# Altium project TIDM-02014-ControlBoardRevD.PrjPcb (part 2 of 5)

## Sheet power_ls.SchDoc: Low-Side Power Rail
size 431 x 279 mm; Date: Not shown in title block; ApprovedBy: Not shown in title block; CheckedBy: Not shown in title block; Author: Not shown in title block; CompanyName: Not shown in title block; DrawnBy: Panacek; Organization: Not shown in title block; Address1: Not shown in title block; Address2: Not shown in title block; Address3: Not shown in title block; Address4: Not shown in title block; DocumentNumber: 3; Revision: Use project parameter SCH_Rev; SheetNumber: 3; SheetTotal: 19; PageSetup: Record=PageOptions¦CenterHorizontal=True¦CenterVertical=True¦PrintScale=1.00¦XCorrection=1.00¦YCorrection=1.00¦PrintKind=0¦BorderSize=5000000¦LeftOffset=0¦BottomOffset=0¦Orientation=2¦PaperLength=1000¦PaperWidth=1000¦Scale=100¦PaperSource=15¦PrintQuality=600¦MediaType=1¦DitherType=10¦PaperKind=Letter¦PrintScaleMode=1
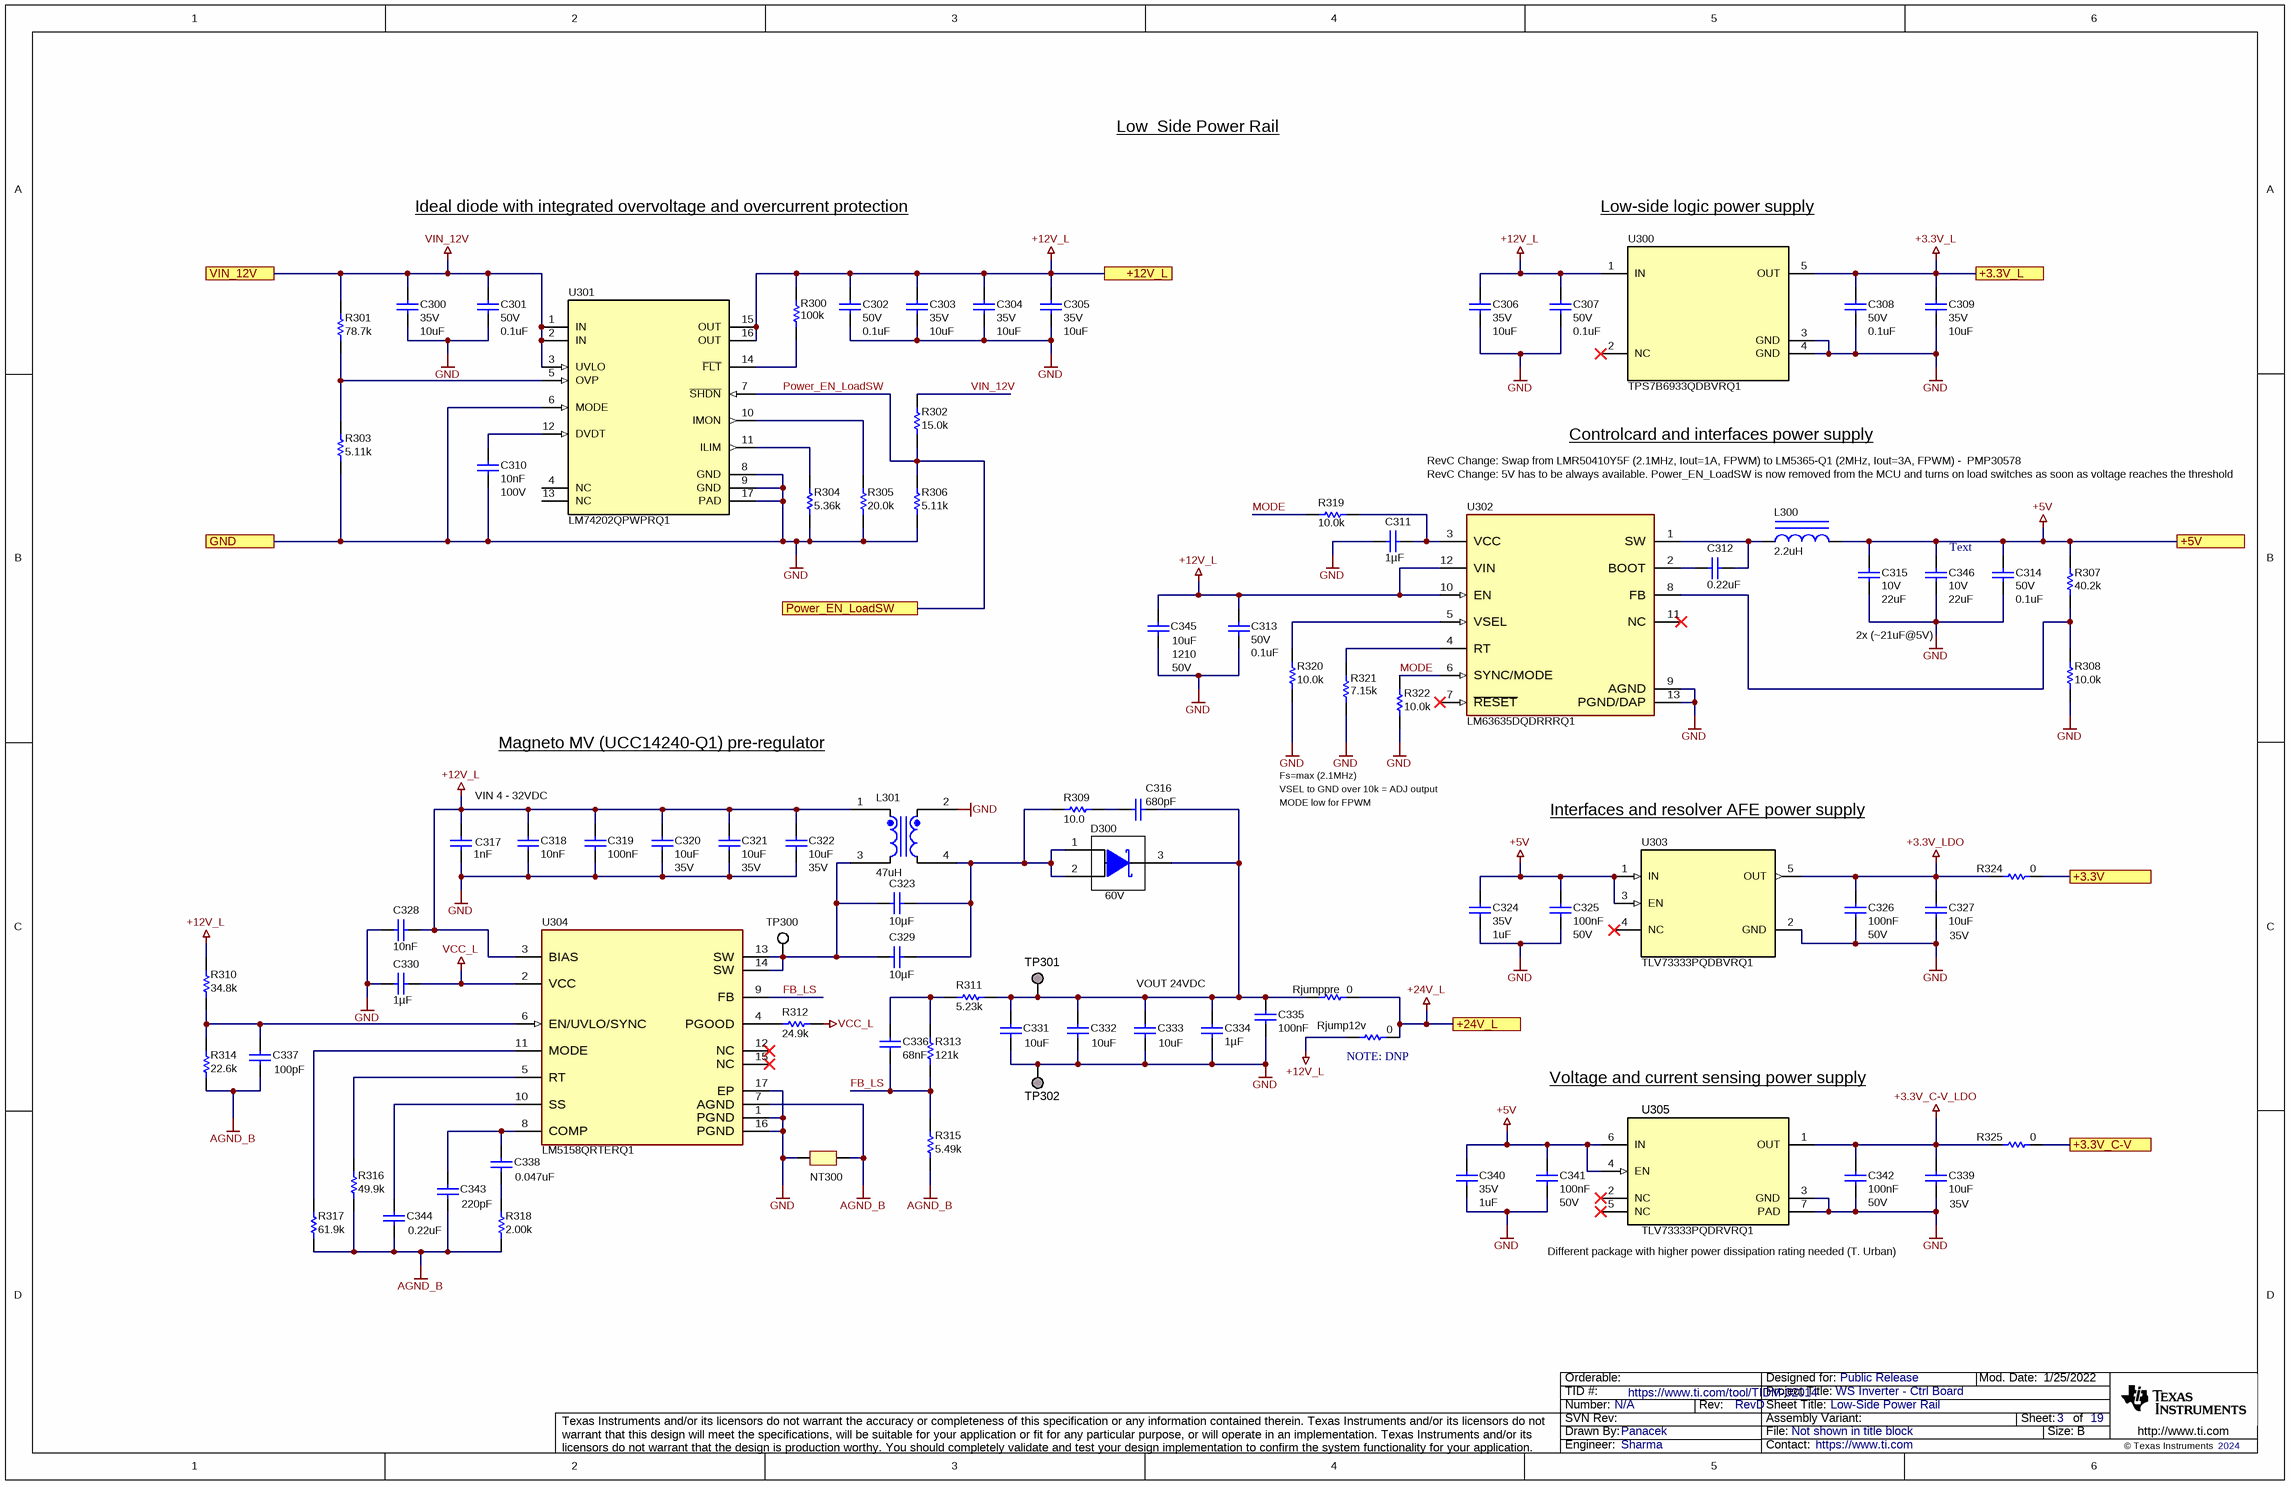
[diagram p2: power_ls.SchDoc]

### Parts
C300  VDC_V: 35V  ValueDisplayed: 10uF  [0603]  (hidden comment: GRM188R6YA106MA73D)
C301  VDC_V: 50V  ValueDisplayed: 0.1uF  [0603]  (hidden comment: CGA3E2X7R1H104K080AA)
C302  VDC_V: 50V  ValueDisplayed: 0.1uF  [0603]  (hidden comment: CGA3E2X7R1H104K080AA)
C303  VDC_V: 35V  ValueDisplayed: 10uF  [0603]  (hidden comment: GRM188R6YA106MA73D)
C304  VDC_V: 35V  ValueDisplayed: 10uF  [0603]  (hidden comment: GRM188R6YA106MA73D)
C305  VDC_V: 35V  ValueDisplayed: 10uF  [0603]  (hidden comment: GRM188R6YA106MA73D)
C306  VDC_V: 35V  ValueDisplayed: 10uF  [0603]  (hidden comment: GRM188R6YA106MA73D)
C307  VDC_V: 50V  ValueDisplayed: 0.1uF  [0603]  (hidden comment: CGA3E2X7R1H104K080AA)
C308  VDC_V: 50V  ValueDisplayed: 0.1uF  [0603]  (hidden comment: CGA3E2X7R1H104K080AA)
C309  VDC_V: 35V  ValueDisplayed: 10uF  [0603]  (hidden comment: GRM188R6YA106MA73D)
C310  Cap_F: 10nF  VDC_V: 100V  [0603]  (hidden comment: CGA3E2X7R2A103K080AA)
C311  Cap_F: 1µF  [0603]  (hidden comment: CGA3E1X7R1V105K080AC)
C312  ValueDisplayed: 0.22uF  [0603]  (hidden comment: GCM188R71E224KA55D)
C313  VDC_V: 50V  ValueDisplayed: 0.1uF  [0603]  (hidden comment: CGA3E2X7R1H104K080AA)
C314  VDC_V: 50V  ValueDisplayed: 0.1uF  [0603]  (hidden comment: CGA3E2X7R1H104K080AA)
C315  VDC_V: 10V  ValueDisplayed: 22uF  [1210_270]  (hidden comment: GRM32ER71A226ME20L)
C316  ValueDisplayed: 680pF  [0603]  (hidden comment: C0603C681J5GACTU)
C317  Cap_F: 1nF  [0603]  (hidden comment: GRM1885C1H102JA01D)
C318  Cap_F: 10nF  [0603]  (hidden comment: CGA3E2X7R2A103K080AA)
C319  Cap_F: 100nF  [0603]  (hidden comment: CGA3E2X7R1H104K080AA)
C320  ValueDisplayed: 10uF  VDC_V: 35V  [0603]  (hidden comment: GRM188R6YA106MA73D)
C321  ValueDisplayed: 10uF  VDC_V: 35V  [0603]  (hidden comment: GRM188R6YA106MA73D)
C322  ValueDisplayed: 10uF  VDC_V: 35V  [0603]  (hidden comment: GRM188R6YA106MA73D)
C323  ValueDisplayed: 10µF  [1206_190]  (hidden comment: CGA5L1X7R1H106K160AC)
C324  VDC_V: 35V  ValueDisplayed: 1uF  [0603]  (hidden comment: CGA3E1X7R1V105K080AC)
C325  Cap_F: 100nF  VDC_V: 50V  [0603]  (hidden comment: CGA3E2X7R1H104K080AA)
C326  Cap_F: 100nF  VDC_V: 50V  [0603]  (hidden comment: CGA3E2X7R1H104K080AA)
C327  ValueDisplayed: 10uF  Value2: 35V  [0603]  (hidden comment: GRM188R6YA106MA73D)
C328  Cap_F: 10nF  [0603]  (hidden comment: CGA3E2X7R2A103K080AA)
C329  ValueDisplayed: 10µF  [1206_190]  (hidden comment: CGA5L1X7R1H106K160AC)
C330  Cap_F: 1µF  [0603]  (hidden comment: CGA3E1X7R1V105K080AC)
C331  ValueDisplayed: 10uF  [1210_270]  (hidden comment: GRM32ER71H106KA12L)
C332  ValueDisplayed: 10uF  [1210_270]  (hidden comment: GRM32ER71H106KA12L)
C333  ValueDisplayed: 10uF  [1210_270]  (hidden comment: GRM32ER71H106KA12L)
C334  Cap_F: 1µF  [0805_HV]  (hidden comment: CGA4J3X7R1H105K125AB)
C335  Cap_F: 100nF  [0603]  (hidden comment: CGA3E2X7R1H104K080AA)
C336  Cap_F: 68nF  [0603]  (hidden comment: CGA3E2X7R1H683K080AA)
C337  ValueDisplayed: 100pF  [0603]  (hidden comment: CGA3E2NP01H101J080AA)
C338  ValueDisplayed: 0.047uF  [0603]  (hidden comment: CGA3E2X7R1H473K080AA)
C339  ValueDisplayed: 10uF  Value2: 35V  [0603]  (hidden comment: GRM188R6YA106MA73D)
C340  VDC_V: 35V  ValueDisplayed: 1uF  [0603]  (hidden comment: CGA3E1X7R1V105K080AC)
C341  Cap_F: 100nF  VDC_V: 50V  [0603]  (hidden comment: CGA3E2X7R1H104K080AA)
C342  Cap_F: 100nF  VDC_V: 50V  [0603]  (hidden comment: CGA3E2X7R1H104K080AA)
C343  ValueDisplayed: 220pF  [0603]  (hidden comment: GCM1885C2A221JA16D)
C344  ValueDisplayed: 0.22uF  [0603]  (hidden comment: GCM188R71E224KA55D)
C345  PackageReference: 1210  Value2: 50V  ValueDisplayed: 10uF  [1210_270]  (hidden comment: GRM32ER71H106KA12L)
C346  VDC_V: 10V  ValueDisplayed: 22uF  [1210_270]  (hidden comment: GRM32ER71A226ME20L)
D300  value 60V  [SOT1289]  (hidden comment: PMEG060V100EPDZ)
L300  ValueDisplayed: 2.2uH  [IHLP-2525CZ-5A]  (hidden comment: IHLP2525CZER2R2M5A)
L301  value 47uH  [MSD1514]  (hidden comment: MSD1514-473MEB)
NT300  Net-Tie  [Net-Tie_10mil]  (value not drawn)  (net tie, no BOM)
R300  ValueDisplayed: 100k  [0603]  (hidden comment: CRCW0603100KFKEA)
R301  ValueDisplayed: 78.7k  [0603]  (hidden comment: CRCW060378K7FKEA)
R302  ValueDisplayed: 15.0k  [0603]  (hidden comment: CRCW060315K0FKEA)
R303  ValueDisplayed: 5.11k  [0603]  (hidden comment: CRCW06035K11FKEA)
R304  ValueDisplayed: 5.36k  [0603]  (hidden comment: CRCW06035K36FKEA)
R305  ValueDisplayed: 20.0k  [0603]  (hidden comment: CRCW060320K0FKEA)
R306  ValueDisplayed: 5.11k  [0603]  (hidden comment: CRCW06035K11FKEA)
R307  ValueDisplayed: 40.2k  [0603]  (hidden comment: CRCW060340K2FKEA)
R308  ValueDisplayed: 10.0k  [0603]  (hidden comment: CRCW060310K0FKEA)
R309  ValueDisplayed: 10.0  [1210]  (hidden comment: CRCW121010R0FKEAHP)
R310  ValueDisplayed: 34.8k  [0603]  (hidden comment: CRCW060334K8FKEA)
R311  ValueDisplayed: 5.23k  [0603]  (hidden comment: CRCW06035K23FKEA)
R312  ValueDisplayed: 24.9k  [0603]  (hidden comment: CRCW060324K9FKEA)
R313  ValueDisplayed: 121k  [0603]  (hidden comment: CRCW0603121KFKEA)
R314  ValueDisplayed: 22.6k  [0603]  (hidden comment: CRCW060322K6FKEA)
R315  ValueDisplayed: 5.49k  [0603]  (hidden comment: CRCW06035K49FKEA)
R316  ValueDisplayed: 49.9k  [0603]  (hidden comment: CRCW060349K9FKEA)
R317  ValueDisplayed: 61.9k  [0603]  (hidden comment: CRCW060361K9FKEA)
R318  ValueDisplayed: 2.00k  [0603]  (hidden comment: CRCW06032K00FKEA)
R319  ValueDisplayed: 10.0k  [0603]  (hidden comment: CRCW060310K0FKEA)
R320  ValueDisplayed: 10.0k  [0603]  (hidden comment: CRCW060310K0FKEA)
R321  ValueDisplayed: 7.15k  [0603]  (hidden comment: CRCW06037K15FKEA)
R322  ValueDisplayed: 10.0k  [0603]  (hidden comment: CRCW060310K0FKEA)
R324  ValueDisplayed: 0  [5106]  (hidden comment: 5106)
R325  ValueDisplayed: 0  [5106]  (hidden comment: 5106)
Rjump12v  ValueDisplayed: 0  [5106]  (hidden comment: 5106)
Rjumppre  ValueDisplayed: 0  [5106]  (hidden comment: 5106)
TP300  5015  [Testpoint_Keystone_Miniature]  (value not drawn)
TP301  RCU-0C  [TE_RCU]  (value not drawn)
TP302  RCU-0C  [TE_RCU]  (value not drawn)
U300  TPS7B6933QDBVRQ1  [DBV0005A_N]
U301  LM74202QPWPRQ1  [PWP0016J_N]
U302  LM63635DQDRRRQ1  [DRR0012E-MFG]
U303  TLV73333PQDBVRQ1  [DBV0005A_N]
U304  LM5158QRTERQ1  [RTE0016K-MFG]
U305  TLV73333PQDRVRQ1  [DRV0006A]

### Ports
+3.3V, +3.3V_C-V, +3.3V_L, +5V, +12V_L, +24V_L, GND, Power_EN_LoadSW, VIN_12V

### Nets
+3.3V: R324.1 ; port +3.3V
+3.3V_C-V: R325.1 ; port +3.3V_C-V
+3.3V_C-V_LDO: C339.1 C342.1 R325.2 U305.1(OUT)
+3.3V_L: C308.1 C309.1 U300.5(OUT) ; port +3.3V_L
+3.3V_LDO: C326.1 C327.1 R324.2 U303.5(OUT)
+5V: C314.1 C315.1 C324.1 C325.1 C340.1 C341.1 C346.1 L300.2 R307.2 U303.1(IN) U303.3(EN) U305.4(EN) U305.6(IN) ; port +5V
+12V_L: C302.1 C303.1 C304.1 C305.1 C306.1 C307.1 C313.1 C317.1 C318.1 C319.1 C320.1 C321.1 C322.2 C328.1 C345.1 L301.1 R300.2 R310.2 Rjump12v.2 U300.1(IN) U301.15(OUT) U301.16(OUT) U302.10(EN) U302.12(VIN) U304.3(BIAS) ; port +12V_L
+24V_L: Rjump12v.1 Rjumppre.1 ; port +24V_L
AGND_B: C337.2 C343.2 C344.2 NT300.2 R314.1 R315.1 R316.1 R317.1 R318.1 U304.7(AGND)
GND: C300.2 C301.2 C302.2 C303.2 C304.2 C305.2 C306.2 C307.2 C308.2 C309.2 C310.2 C311.1 C313.2 C314.2 C315.2 C317.2 C318.2 C319.2 C320.2 C321.2 C322.1 C324.2 C325.2 C326.2 C327.2 C328.2 C330.1 C331.2 C332.2 C333.2 C334.2 C335.2 C339.2 C340.2 C341.2 C342.2 C345.2 C346.2 L301.2 NT300.1 R303.1 R304.1 R305.1 R306.1 R308.1 R320.1 R321.1 R322.1 TP302.1 U300.3(GND) U300.4(GND) U301.6(MODE) U301.8(GND) U301.9(GND) U301.17(PAD) U302.9(AGND) U302.13(PGND/DAP) U303.2(GND) U304.1(PGND) U304.16(PGND) U304.17(EP) U305.3(GND) U305.7(PAD) ; port GND
VCC_L: C330.2 R312.2 U304.2(VCC)
VIN_12V: C300.1 C301.1 R301.2 R302.2 U301.1(IN) U301.2(IN) U301.3(UVLO) ; port VIN_12V
FB_LS: C336.2 R313.1 R315.2 U304.9(FB)  [project net FB_LS_3]
MODE: R319.2 R322.2 U302.6(SYNC/MODE)  [project net MODE_3]
Power_EN_LoadSW: R302.1 R306.2 U301.7(~{SHDN}) ; port Power_EN_LoadSW
NetC310_1: C310.1 U301.12(DVDT)
NetC311_2: C311.2 R319.1 U302.3(VCC)
NetC312_1: C312.1 U302.2(BOOT)
NetC312_2: C312.2 L300.1 U302.1(SW)
NetC316_1: C316.1 C331.1 C332.1 C333.1 C334.1 C335.1 D300.3(K) R311.2 Rjumppre.2 TP301.1
NetC316_2: C316.2 R309.2
NetC323_1: C323.1 C329.1 D300.1(A) D300.2(A) L301.4 R309.1
NetC323_2: C323.2 C329.2 L301.3 TP300.1 U304.13(SW) U304.14(SW)
NetC336_1: C336.1 R311.1 R313.2
NetC337_1: C337.1 R310.1 R314.2 U304.6(EN/UVLO/SYNC)
NetC338_1: C338.1 C343.1 U304.8(COMP)
NetC338_2: C338.2 R318.2
NetC344_1: C344.1 U304.10(SS)
NetR300_1: R300.1 U301.14(~{FLT})
NetR301_1: R301.1 R303.2 U301.5(OVP)
NetR304_2: R304.2 U301.11(ILIM)
NetR305_2: R305.2 U301.10(IMON)
NetR307_1: R307.1 R308.2 U302.8(FB)
NetR312_1: R312.1 U304.4(PGOOD)
NetR316_2: R316.2 U304.5(RT)
NetR317_2: R317.2 U304.11(MODE)
NetR320_2: R320.2 U302.5(VSEL)
NetR321_2: R321.2 U302.4(RT)

Not connected (* = marked no-connect by the designer): U300 2(NC)*; U301 4(NC) 13(NC); U302 7(~{RESET})* 11(NC)*; U303 4(NC)*; U304 12(NC)* 15(NC)*; U305 2(NC)* 5(NC)*

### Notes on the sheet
- Low  Side Power Rail
- Ideal diode with integrated overvoltage and overcurrent protection
- Low-side logic power supply
- Controlcard and interfaces power supply
- RevC Change: Swap from LMR50410Y5F (2.1MHz, Iout=1A, FPWM) to LM5365-Q1 (2MHz, Iout=3A, FPWM) -  PMP30578
- RevC Change: 5V has to be always available. Power_EN_LoadSW is now removed from the MCU and turns on load switches as soon as voltage reaches the threshold
- Text
- 2x (|1uF@5V)
- Magneto MV (UCC14240-Q1) pre-regulator
- VIN 4 - 32VDC
- Fs=max (2.1MHz)
- VSEL to GND over 10k = ADJ output
- MODE low for FPWM
- Interfaces and resolver AFE power supply
- VOUT 24VDC
- (near Rjump12v) NOTE: DNP
- Voltage and current sensing power supply
- (near U305) Different package with higher power dissipation rating needed (T. Urban)

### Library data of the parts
C300 C303-C306 C309 = CMP-0007355-6: CAP, CERM, 10 uF, 35 V, +/- 20%, X5R, 0603; Manufacturer: Murata; TaMin_C: -55°C; Polarized: N; SizeAreaWB_mm2: 4.68; Value1: Unknown; U/M: EA; Value: 10uF; TaMax_C: 85°C; SizeZ_mm: 1; SizeX_mm: 1.6; SizeY_mm: 0.8; SizeArea_mm2: 1.28; Cap_F: 10µF; AEC Category: Q200
C301 C302 C307 C308 C313 C314 = CMP-0007078-4: CAP, CERM, 0.1 uF, 50 V, +/- 10%, X7R, AEC-Q200 Grade 1, 0603; Manufacturer: TDK; TaMin_C: -55°C; ESR_ohm: 29.6m; Polarized: N; SizeAreaWB_mm2: 4.68; Value1: 0.0296 ohm; U/M: EA; Value: 0.1uF; TaMax_C: 125°C; SizeZ_mm: 1; SizeX_mm: 1.6; SizeY_mm: 0.8; SizeArea_mm2: 1.28; AEC Qualified: Y; Cap_F: 100nF; IRMS_A: 971.99mA; AEC Category: Q200
C310 = CMP-0007082-4: CAP, CERM, 0.01 uF, 100 V, +/- 10%, X7R, AEC-Q200 Grade 1, 0603; Manufacturer: TDK; TaMin_C: -55°C; Polarized: N; SizeAreaWB_mm2: 4.68; U/M: EA; Value: 0.01uF; TaMax_C: 125°C; SizeZ_mm: 1; SizeX_mm: 1.6; SizeY_mm: 0.8; SizeArea_mm2: 1.28; AEC Qualified: Y; AEC Category: Q200; ESR_ohm: 0.2354; IRMS_A: 396.995mA; Value1: 0.235428 ohm
C311 C330 = CMP-0007067-4: CAP, CERM, 1 uF, 35 V, +/- 10%, X7R, AEC-Q200 Grade 1, 0603; Manufacturer: TDK; TaMin_C: -55°C; ESR_ohm: 5.522m; Polarized: N; SizeAreaWB_mm2: 4.68; Value1: 0.005522 ohm; U/M: EA; Value: 1uF; TaMax_C: 125°C; SizeZ_mm: 1; SizeX_mm: 1.6; SizeY_mm: 0.8; Value2: 35V; SizeArea_mm2: 1.28; AEC Qualified: Y; IRMS_A: 2.2162A; AEC Category: Q200
C312 C344 = CMP-0007140-4: CAP, CERM, 0.22 uF, 25 V, +/- 10%, X7R, AEC-Q200 Grade 1, 0603; Manufacturer: MuRata; TaMin_C: -55°C; Polarized: N; SizeAreaWB_mm2: 4.68; Value1: Unknown; U/M: EA; Value: 0.22uF; TaMax_C: 125°C; SizeZ_mm: 1; SizeX_mm: 1.6; Value2: 25V; SizeArea_mm2: 1.28; AEC Qualified: Y; Cap_F: 220nF; AEC Category: Q200; SizeY_mm: 0.8
C315 C346 = CMP-0009219-2: CAP, CERM, 22 uF, 10 V, +/- 10%, X7R, 1210; Manufacturer: MuRata; TaMin_C: -55°C; ESR_ohm: 2m; Polarized: N; SizeAreaWB_mm2: 14.7; Value1: 0.002 ohm; U/M: EA; Value: 22uF; TaMax_C: 125°C; SizeZ_mm: 2.7; SizeX_mm: 3.2; SizeY_mm: 2.5; Cap_Case: 1210; SizeArea_mm2: 8; Cap_F: 22µF; IRMS_A: 3.2A; AEC Category: Q200
C316 = CMP-0006959-4: CAP, CERM, 680 pF, 50 V, +/- 5%, C0G/NP0, 0603; Manufacturer: Kemet; TaMin_C: -55°C; Polarized: N; SizeAreaWB_mm2: 4.68; Value1: Unknown; U/M: EA; Value: 680pF; TaMax_C: 125°C; SizeZ_mm: 1; SizeX_mm: 1.6; SizeY_mm: 0.8; Value2: 50V; SizeArea_mm2: 1.28; AEC Category: Q200
C317 = CMP-0007173-4: CAP, CERM, 1000 pF, 50 V, +/- 5%, C0G/NP0, 0603; Manufacturer: MuRata; TaMin_C: -55°C; Polarized: N; SizeAreaWB_mm2: 4.68; Value1: Unknown; U/M: EA; Value: 1000pF; TaMax_C: 125°C; SizeZ_mm: 1; SizeX_mm: 1.6; SizeY_mm: 0.8; Value2: 50V; SizeArea_mm2: 1.28; AEC Category: Q200
C318 = CMP-0007082-4: CAP, CERM, 0.01 uF, 100 V, +/- 10%, X7R, AEC-Q200 Grade 1, 0603; Manufacturer: TDK; TaMin_C: -55°C; Polarized: N; SizeAreaWB_mm2: 4.68; Value1: 0.235428 ohm; U/M: EA; Value: 0.01uF; TaMax_C: 125°C; SizeZ_mm: 1; SizeX_mm: 1.6; SizeY_mm: 0.8; Value2: 100V; SizeArea_mm2: 1.28; AEC Qualified: Y; AEC Category: Q200; ESR_ohm: 0.2354; IRMS_A: 396.995mA
C319 C335 = CMP-0007078-4: CAP, CERM, 0.1 uF, 50 V, +/- 10%, X7R, AEC-Q200 Grade 1, 0603; Manufacturer: TDK; TaMin_C: -55°C; ESR_ohm: 29.6m; Polarized: N; SizeAreaWB_mm2: 4.68; Value1: 0.0296 ohm; U/M: EA; Value: 0.1uF; TaMax_C: 125°C; SizeZ_mm: 1; SizeX_mm: 1.6; SizeY_mm: 0.8; Value2: 50V; SizeArea_mm2: 1.28; AEC Qualified: Y; IRMS_A: 971.99mA; AEC Category: Q200
C320-C322 = CMP-0007355-6: CAP, CERM, 10 uF, 35 V, +/- 20%, X5R, 0603; Manufacturer: Murata; TaMax_C: 85°C; Value1: Unknown; TaMin_C: -55°C; Value: 10uF; SizeZ_mm: 1; SizeArea_mm2: 1.28; AEC Category: Q200; Cap_F: 10µF; SizeY_mm: 0.8; AEC Qualified: N; SizeX_mm: 1.6; SizeAreaWB_mm2: 4.68; U/M: EA
C323 C329 = CMP-0085950-1: CAP, CERM, 10 µF, 50 V,+/- 10%, X7R, AEC-Q200 Grade 1, 1206; Manufacturer: TDK; SizeZ_mm: 1.9; Value: 10uF; Value2: 50V; Cap_Case: 1206; AEC Grade: 1; TaMin_C: -55°C; U/M: EA; SizeArea_mm2: 5.12; TaMax_C: 125°C; AEC Qualified: Y; AEC Category: Q200; SizeX_mm: 3.2; SizeY_mm: 1.6; Polarized: N; SizeAreaWB_mm2: 10.92
C324 C340 = CMP-0007067-4: CAP, CERM, 1 uF, 35 V, +/- 10%, X7R, AEC-Q200 Grade 1, 0603; Manufacturer: TDK; TaMin_C: -55°C; Polarized: N; SizeAreaWB_mm2: 4.68; Value1: 0.005522 ohm; U/M: EA; Value: 1uF; TaMax_C: 125°C; SizeZ_mm: 1; SizeX_mm: 1.6; SizeY_mm: 0.8; SizeArea_mm2: 1.28; AEC Qualified: Y; Cap_F: 1µF; AEC Category: Q200; ESR_ohm: 5.522m; IRMS_A: 2.2162A
C325 C326 C341 C342 = CMP-0007078-4: CAP, CERM, 0.1 uF, 50 V, +/- 10%, X7R, AEC-Q200 Grade 1, 0603; Manufacturer: TDK; TaMin_C: -55°C; Polarized: N; SizeAreaWB_mm2: 4.68; Value1: 0.0296 ohm; U/M: EA; Value: 0.1uF; TaMax_C: 125°C; SizeZ_mm: 1; SizeX_mm: 1.6; SizeY_mm: 0.8; SizeArea_mm2: 1.28; AEC Qualified: Y; AEC Category: Q200; ESR_ohm: 29.6m; IRMS_A: 971.99mA
C327 C339 = CMP-0007355-6: CAP, CERM, 10 uF, 35 V, +/- 20%, X5R, 0603; Manufacturer: Murata; Polarized: N; Value: 10uF; U/M: EA; Cap_F: 10µF; Value1: Unknown; TaMin_C: -55°C; TaMax_C: 85°C; SizeArea_mm2: 1.28; SizeAreaWB_mm2: 4.68; SizeX_mm: 1.6; SizeY_mm: 0.8; SizeZ_mm: 1; AEC Category: Q200
C328 = CMP-0007082-4: CAP, CERM, 0.01 uF, 100 V, +/- 10%, X7R, AEC-Q200 Grade 1, 0603; Manufacturer: TDK; TaMin_C: -55°C; Polarized: N; SizeAreaWB_mm2: 4.68; Value1: 0.235428 ohm; U/M: EA; Value: 0.01uF; TaMax_C: 125°C; SizeZ_mm: 1; SizeX_mm: 1.6; Value2: 100V; SizeArea_mm2: 1.28; AEC Qualified: Y; AEC Category: Q200; SizeY_mm: 0.8; ESR_ohm: 0.2354; IRMS_A: 396.995mA
C331-C333 = CMP-0009226-3: CAP, CERM, 10 uF, 50 V, +/- 10%, X7R, 1210; Manufacturer: MuRata; TaMin_C: -55°C; Polarized: N; SizeAreaWB_mm2: 14.7; Value1: Unknown; U/M: EA; Value: 10uF; TaMax_C: 125°C; SizeZ_mm: 2.7; SizeX_mm: 3.2; SizeY_mm: 2.5; Cap_Case: 1210; Value2: 50V; SizeArea_mm2: 8; Cap_F: 10µF; AEC Category: Q200
C334 = CMP-0007976-2: CAP, CERM, 1 uF, 50 V, +/- 10%, X7R, AEC-Q200 Grade 1, 0805; Manufacturer: TDK; TaMin_C: -55°C; Polarized: N; SizeAreaWB_mm2: 6.75; Value1: 0.008782 ohm; U/M: EA; Value: 1uF; TaMax_C: 125°C; SizeZ_mm: 1.45; SizeX_mm: 2; SizeY_mm: 1.25; Cap_Case: 0805; Value2: 50V; SizeArea_mm2: 2.5; AEC Qualified: Y; AEC Grade: 1; AEC Category: Q200; ESR_ohm: 8.782m; IRMS_A: 2.2049A
C336 = CMP-0007080-5: CAP, CERM, 0.068 uF, 50 V, +/- 10%, X7R, AEC-Q200 Grade 1, 0603; Manufacturer: TDK; TaMin_C: -55°C; Polarized: N; SizeAreaWB_mm2: 4.68; Value1: 0.035979 ohm; U/M: EA; TaMax_C: 125°C; SizeZ_mm: 1; SizeX_mm: 1.6; SizeY_mm: 0.8; Value2: 50V; SizeArea_mm2: 1.28; AEC Qualified: Y; AEC Category: Q200; ESR_ohm: 35.979m; IRMS_A: 886.483mA
C337 = CMP-0007075-4: CAP, CERM, 100 pF, 50 V, +/- 5%, C0G/NP0, AEC-Q200 Grade 0, 0603; Manufacturer: TDK; TaMin_C: -55°C; Polarized: N; SizeAreaWB_mm2: 4.68; Value1: Unknown; U/M: EA; Value: 100pF; TaMax_C: 150°C; SizeZ_mm: 1; SizeX_mm: 1.6; SizeY_mm: 0.8; Value2: 50V; SizeArea_mm2: 1.28; AEC Qualified: Y; AEC Grade: 0; AEC Category: Q200
C338 = CMP-0007079-4: CAP, CERM, 0.047 uF, 50 V, +/- 10%, X7R, AEC-Q200 Grade 1, 0603; Manufacturer: TDK; TaMin_C: -55°C; ESR_ohm: 49.007m; Polarized: N; SizeAreaWB_mm2: 4.68; Value1: 0.049007 ohm; U/M: EA; TaMax_C: 125°C; SizeZ_mm: 1; SizeX_mm: 1.6; SizeY_mm: 0.8; Value2: 50V; SizeArea_mm2: 1.28; AEC Qualified: Y; Cap_F: 47nF; IRMS_A: 767.528mA; AEC Category: Q200
C343 = CMP-0860912-1: CAP, CERM, 220 pF, 100 V,+/- 5%, C0G/NP0, AEC-Q200 Grade 1, 0603; Manufacturer: MuRata; TaMin_C: -55°C; Polarized: N; SizeAreaWB_mm2: 4.68; U/M: EA; Value: 220pF; TaMax_C: 125°C; SizeZ_mm: 1; SizeX_mm: 1.6; SizeY_mm: 0.8; Value2: 100V; SizeArea_mm2: 1.28; AEC Qualified: Y; AEC Category: Q200
C345 = CMP-0009226-3: CAP, CERM, 10 uF, 50 V, +/- 10%, X7R, 1210; Manufacturer: MuRata; TaMin_C: -55°C; Polarized: N; SizeAreaWB_mm2: 14.7; Value1: Unknown; U/M: EA; Value: 10uF; TaMax_C: 125°C; SizeZ_mm: 2.7; SizeX_mm: 3.2; SizeY_mm: 2.5; SizeArea_mm2: 8; Cap_F: 10µF; AEC Category: Q200
D300 = CMP-0028984-3: Diode, Schottky, 60 V, 10 A, AEC-Q101, CFP15; Manufacturer: Nexperia; Io_A: 10A; SizeAreaWB_mm2: 53.55; TJmax_C: 175°C; SizeZ_mm: 0.82; SizeX_mm: 6.5; SizeY_mm: 4.3; Vf_V: 560mV; Value2: 0.56V; SizeArea_mm2: 27.95; AEC Qualified: Y; AEC Category: Q101
L300 = CMP-0063383-1: Inductor, Shielded, 2.2 uH, 8.1 A, 0.0183 ohm, AEC-Q200 Grade 1, SMD; Manufacturer: Vishay-Dale; Isat: 10.8A @ 20% inductance drop; Irms: 8.1A @ 40C rise; SizeAreaWB_mm2: 75.0442; DCR_ohm: 18.3m; Value: 2.2uH; Imax_A: 8.1A; SizeZ_mm: 3; SizeX_mm: 6.86; SizeY_mm: 6.47; SizeArea_mm2: 44.3842; Ind_H: 2.2µH; AEC Qualified: Y; AEC Grade: 1; AEC Category: Q200; Green_Lifecycle: Active; Green_REACh: Passed
L301 = CMP-0080788-1: Coupled inductor, 47 µH, 7.5 A, 0.065 ohm, SMD; Manufacturer: Coilcraft; SizeAreaWB_mm2: 289; DCR_ohm: 65m; SizeZ_mm: 14.2; SizeX_mm: 15; SizeArea_mm2: 225; Ind_H: 47µH; AEC Qualified: N; AEC Category: Q200
NT300 = CMP-0078142-6: Single point connection between nets.
R300 = CMP-0021990-4: RES, 100 k, 1%, 0.1 W, AEC-Q200 Grade 0, 0603; Manufacturer: Vishay-Dale; Power_W: 100mW; TempCo: 100 ppm/C; Value: 100k; EIA_Code: E96; SizeX_mm: 1.6; SizeY_mm: 0.8; SizeZ_mm: 1; Value2: 0.1W; SizeArea_mm2: 1.28; AEC Qualified: Y; VDC_V: 75V; AEC Category: Q200; AEC Grade: 0
R301 = CMP-0022597-4: RES, 78.7 k, 1%, 0.1 W, AEC-Q200 Grade 0, 0603; Manufacturer: Vishay-Dale; Power_W: 100mW; TempCo: 100 ppm/C; Value_Code: 78k7; Value: 78.7k; EIA_Code: E96; SizeX_mm: 1.6; SizeY_mm: 0.8; SizeZ_mm: 1; Value2: 0.1W; SizeArea_mm2: 1.28; AEC Qualified: Y; VDC_V: 75V; AEC Category: Q200; AEC Grade: 0
R302 = CMP-0022066-4: RES, 15.0 k, 1%, 0.1 W, AEC-Q200 Grade 0, 0603; Manufacturer: Vishay-Dale; Value: 15.0k; Res_ohm: 15k; Value_Code: 15k0; Power_W: 100mW; Value2: 0.1W; VDC_V: 75V; TempCo: 100 ppm/C; SizeArea_mm2: 1.28; SizeX_mm: 1.6; SizeY_mm: 0.8; SizeZ_mm: 1; EIA_Code: E96; AEC Category: Q200; AEC Qualified: Y; AEC Grade: 0
R303 = CMP-0022509-4: RES, 5.11 k, 1%, 0.1 W, AEC-Q200 Grade 0, 0603; Manufacturer: Vishay-Dale; Power_W: 100mW; TempCo: 100 ppm/C; Value_Code: 5k11; Value: 5.11k; EIA_Code: E96; SizeX_mm: 1.6; SizeY_mm: 0.8; SizeZ_mm: 1; Value2: 0.1W; SizeArea_mm2: 1.28; AEC Qualified: Y; VDC_V: 75V; AEC Category: Q200; AEC Grade: 0
R304 = CMP-0022511-4: RES, 5.36 k, 1%, 0.1 W, AEC-Q200 Grade 0, 0603; Manufacturer: Vishay-Dale; Power_W: 100mW; TempCo: 100 ppm/C; Value_Code: 5k36; Value: 5.36k; EIA_Code: E96; SizeX_mm: 1.6; SizeY_mm: 0.8; SizeZ_mm: 1; Value2: 0.1W; SizeArea_mm2: 1.28; AEC Qualified: Y; VDC_V: 75V; AEC Category: Q200; AEC Grade: 0
R305 = CMP-0022204-4: RES, 20.0 k, 1%, 0.1 W, AEC-Q200 Grade 0, 0603; Manufacturer: Vishay-Dale; Power_W: 100mW; TempCo: 100 ppm/C; Value_Code: 20k0; Value: 20.0k; EIA_Code: E96; Res_ohm: 20k; SizeX_mm: 1.6; SizeY_mm: 0.8; SizeZ_mm: 1; Value2: 0.1W; SizeArea_mm2: 1.28; AEC Qualified: Y; VDC_V: 75V; AEC Category: Q200; AEC Grade: 0
R306 = CMP-0022509-4: RES, 5.11 k, 1%, 0.1 W, AEC-Q200 Grade 0, 0603; Manufacturer: Vishay-Dale; Value: 5.11k; Value_Code: 5k11; Power_W: 100mW; Value2: 0.1W; VDC_V: 75V; TempCo: 100 ppm/C; SizeArea_mm2: 1.28; SizeX_mm: 1.6; SizeY_mm: 0.8; SizeZ_mm: 1; EIA_Code: E96; AEC Category: Q200; AEC Qualified: Y; AEC Grade: 0
R307 = CMP-0022410-4: RES, 40.2 k, 1%, 0.1 W, AEC-Q200 Grade 0, 0603; Manufacturer: Vishay-Dale; Power_W: 100mW; TempCo: 100 ppm/C; Value_Code: 40k2; Value: 40.2k; EIA_Code: E96; SizeX_mm: 1.6; SizeY_mm: 0.8; SizeZ_mm: 1; Value2: 0.1W; SizeArea_mm2: 1.28; AEC Qualified: Y; VDC_V: 75V; AEC Category: Q200; AEC Grade: 0
R308 R319 R320 R322 = CMP-0021998-4: RES, 10.0 k, 1%, 0.1 W, AEC-Q200 Grade 0, 0603; Manufacturer: Vishay-Dale; Power_W: 100mW; TempCo: 100 ppm/C; Value_Code: 10k0; Value: 10.0k; EIA_Code: E96; Res_ohm: 10k; SizeX_mm: 1.6; SizeY_mm: 0.8; SizeZ_mm: 1; Value2: 0.1W; SizeArea_mm2: 1.28; AEC Qualified: Y; VDC_V: 75V; AEC Category: Q200; AEC Grade: 0
R309 = CMP-0015019-3: RES, 10.0, 1%, 0.75 W, AEC-Q200 Grade 0, 1210; Manufacturer: Vishay-Dale; Power_W: 750mW; TempCo: 100 ppm/C; SizeAreaWB_mm2: 14.7; Value_Code: 10R0; Value: 10.0; EIA_Code: E96; Res_ohm: 10; SizeX_mm: 3.2; SizeY_mm: 2.5; SizeZ_mm: 1.35; Value2: 0.75W; SizeArea_mm2: 8; AEC Qualified: Y; AEC Grade: 0; AEC Category: Q200
R310 = CMP-0022347-4: RES, 34.8 k, 1%, 0.1 W, AEC-Q200 Grade 0, 0603; Manufacturer: Vishay-Dale; Power_W: 100mW; TempCo: 100 ppm/C; Value_Code: 34k8; Value: 34.8k; EIA_Code: E96; SizeX_mm: 1.6; SizeY_mm: 0.8; SizeZ_mm: 1; Value2: 0.1W; SizeArea_mm2: 1.28; AEC Qualified: Y; VDC_V: 75V; AEC Category: Q200; AEC Grade: 0
R311 = CMP-0022510-4: RES, 5.23 k, 1%, 0.1 W, AEC-Q200 Grade 0, 0603; Manufacturer: Vishay-Dale; Power_W: 100mW; TempCo: 100 ppm/C; Value_Code: 5k23; Value: 5.23k; EIA_Code: E96; SizeX_mm: 1.6; SizeY_mm: 0.8; SizeZ_mm: 1; Value2: 0.1W; SizeArea_mm2: 1.28; AEC Qualified: Y; VDC_V: 75V; AEC Category: Q200; AEC Grade: 0
R312 = CMP-0022237-4: RES, 24.9 k, 1%, 0.1 W, AEC-Q200 Grade 0, 0603; Manufacturer: Vishay-Dale; Power_W: 100mW; TempCo: 100 ppm/C; Value_Code: 24k9; Value: 24.9k; EIA_Code: E96; SizeX_mm: 1.6; SizeY_mm: 0.8; SizeZ_mm: 1; Value2: 0.1W; SizeArea_mm2: 1.28; AEC Qualified: Y; VDC_V: 75V; AEC Category: Q200; AEC Grade: 0
R313 = CMP-0022024-4: RES, 121 k, 1%, 0.1 W, AEC-Q200 Grade 0, 0603; Manufacturer: Vishay-Dale; Power_W: 100mW; TempCo: 100 ppm/C; Value: 121k; EIA_Code: E96; SizeX_mm: 1.6; SizeY_mm: 0.8; SizeZ_mm: 1; Value2: 0.1W; SizeArea_mm2: 1.28; AEC Qualified: Y; VDC_V: 75V; AEC Category: Q200; AEC Grade: 0
R314 = CMP-0022221-4: RES, 22.6 k, 1%, 0.1 W, AEC-Q200 Grade 0, 0603; Manufacturer: Vishay-Dale; Power_W: 100mW; TempCo: 100 ppm/C; Value_Code: 22k6; Value: 22.6k; EIA_Code: E96; SizeX_mm: 1.6; SizeY_mm: 0.8; SizeZ_mm: 1; Value2: 0.1W; SizeArea_mm2: 1.28; AEC Qualified: Y; VDC_V: 75V; AEC Category: Q200; AEC Grade: 0
R315 = CMP-0022512-4: RES, 5.49 k, 1%, 0.1 W, AEC-Q200 Grade 0, 0603; Manufacturer: Vishay-Dale; Power_W: 100mW; TempCo: 100 ppm/C; Value_Code: 5k49; Value: 5.49k; EIA_Code: E96; SizeX_mm: 1.6; SizeY_mm: 0.8; SizeZ_mm: 1; Value2: 0.1W; SizeArea_mm2: 1.28; AEC Qualified: Y; VDC_V: 75V; AEC Category: Q200; AEC Grade: 0
R316 = CMP-0022447-4: RES, 49.9 k, 1%, 0.1 W, AEC-Q200 Grade 0, 0603; Manufacturer: Vishay-Dale; Power_W: 100mW; TempCo: 100 ppm/C; Value_Code: 49k9; Value: 49.9k; EIA_Code: E96; SizeX_mm: 1.6; SizeY_mm: 0.8; SizeZ_mm: 1; Value2: 0.1W; SizeArea_mm2: 1.28; AEC Qualified: Y; VDC_V: 75V; AEC Category: Q200; AEC Grade: 0
R317 = CMP-0022536-4: RES, 61.9 k, 1%, 0.1 W, AEC-Q200 Grade 0, 0603; Manufacturer: Vishay-Dale; Power_W: 100mW; TempCo: 100 ppm/C; Value_Code: 61k9; Value: 61.9k; EIA_Code: E96; SizeX_mm: 1.6; SizeY_mm: 0.8; SizeZ_mm: 1; Value2: 0.1W; SizeArea_mm2: 1.28; AEC Qualified: Y; VDC_V: 75V; AEC Category: Q200; AEC Grade: 0
R318 = CMP-0022268-4: RES, 2.00 k, 1%, 0.1 W, AEC-Q200 Grade 0, 0603; Manufacturer: Vishay-Dale; Power_W: 100mW; TempCo: 100 ppm/C; Value_Code: 2k00; Value: 2.00k; Res_ohm: 2k; SizeX_mm: 1.6; SizeY_mm: 0.8; SizeZ_mm: 1; Value2: 0.1W; SizeArea_mm2: 1.28; AEC Qualified: Y; VDC_V: 75V; AEC Grade: 0; AEC Category: Q200; EIA_Code: E96
R321 = CMP-0022599-4: RES, 7.15 k, 1%, 0.1 W, AEC-Q200 Grade 0, 0603; Manufacturer: Vishay-Dale; Value: 7.15k; Value_Code: 7k15; Power_W: 100mW; Value2: 0.1W; VDC_V: 75V; TempCo: 100 ppm/C; SizeArea_mm2: 1.28; SizeX_mm: 1.6; SizeY_mm: 0.8; SizeZ_mm: 1; EIA_Code: E96; AEC Category: Q200; AEC Qualified: Y; AEC Grade: 0
R324 R325 Rjump12v Rjumppre = CMP-0020833-2: RES, 0, 1%, 0.5 W, 0805; Manufacturer: Keystone; SizeArea_mm2: 2.5; AEC Qualified: N; AEC Category: Q200; Value: 0; SizeZ_mm: 0.84; SizeY_mm: 1.25; Power_W: 500mW; Value2: 0.5W; SizeX_mm: 2; TempCo: ppm/C; U/M: EA
TP300 = CMP-0055152-2: Test Point, Miniature, SMT; Manufacturer: Keystone Electronics; CNHeader: FALSE; Green_Lifecycle: Active; Green_REACh: Passed; CT: TRUE
TP301 TP302 = CMP-0067620-1: PC Test Point, SMT; Manufacturer: TE Connectivity
U300 = CMP-0079175-1: Automotive High-Voltage Ultralow-IQ Low-Dropout Regulator, DBV0005A (SOT-23-5); Alternate Manufacturer: Texas Instruments; SizeAreaWB_mm2: 14.82; SizeZ_mm: 1.45; SizeX_mm: 2.8; SizeY_mm: 2.9; SizeArea_mm2: 8.12; CompType: IC; AEC Qualified: Y; AEC Category: Q200
U301 = CMP-0086311-1: 40V, 2A Integrated Ideal Diode with Over-Voltage & Over-Current protection, PWP0016J (HTSSOP-16); Alternate Manufacturer: Texas Instruments; CompType: IC; SizeAreaWB_mm2: 58.8; AEC Qualified: N; SizeZ_mm: 1.2; SizeY_mm: 5; AEC Category: Q200; SizeX_mm: 6.4; SizeArea_mm2: 32
U302 = CMP-0097736-1: Buck Switching Regulator IC Positive Adjustable 1V 1 Output 3.25A 12-WFDFN Exposed Pad; Manufacturer: Texas Instruments; Min Supply Voltage: 3.5V; Standoff Height: 0mm; TaMax_C: +125°C; AEC Grade: Grade 1; TJmax_C: +150°C; AEC Qualified: Yes; Max Supply Voltage: 36V; Nominal Supply Current: 23uA; Max Duty Cycle: 98%; Switching Frequency: 400/2100/250-2200kHz; TaMin_C: -40°C; Output Voltage: 3.3/5/1-20V; Output Type: Fixed,AdjustableProgrammable; SizeZ_mm: 0.8mm; Number Of Outputs: 1
U303 = CMP-0860155-1: Automotive capacitor-free 300-mA LDO regulator with foldback current limit for portable devices, DBV0005A (SOT-23-5); Manufacturer: Texas Instruments; SizeAreaWB_mm2: 14.82; SizeArea_mm2: 8.12; SizeY_mm: 2.9; CompType: IC; SizeZ_mm: 1.45; SizeX_mm: 2.8; AEC Category: Q200; AEC Qualified: Y
U304 = CMP-0091836-5: 2.2-MHz Wide VIN 85-V Boost/Sepic/Flyback Converter with Dual Random Spread Spectrum; Manufacturer: Texas Instruments; Switching Frequency: 100-2200kHz; AEC Qualified: Yes; AEC Grade: Grade 1; Max Supply Voltage: 60V; Number Of Outputs: 1; Output Type: AdjustableProgrammable; TaMax_C: +125°C; Nominal Supply Current: 670uA; CompType: IC; Switching Topology: Boost,Flyback; AEC Category: Q200; Output Voltage: 83V; Standoff Height: 0mm; TJmax_C: +150°C; Max Duty Cycle: 96%; TaMin_C: -40°C; SizeZ_mm: 0.8mm; Min Supply Voltage: 1.5V
U305 = CMP-0078865-1: Capacitor-Free, 300-mA, Low-Dropout Regulator for Automotive, DRV0006A (WSON-6); Manufacturer: Texas Instruments; SizeAreaWB_mm2: 9; SizeArea_mm2: 4; SizeY_mm: 2; CompType: IC; SizeZ_mm: 0.8; AEC Category: Q200; AEC Qualified: Y

## Sheet power_lem.SchDoc: LEM sensors power supply
size 431 x 279 mm; Date: Not shown in title block; ApprovedBy: Not shown in title block; CheckedBy: Not shown in title block; Author: Not shown in title block; CompanyName: Not shown in title block; DrawnBy: Panacek; Engineer: Not shown in title block; Organization: Not shown in title block; Address1: Not shown in title block; Address2: Not shown in title block; Address3: Not shown in title block; Address4: Not shown in title block; DocumentNumber: 4; Revision: Use project parameter SCH_Rev; SheetNumber: 4; SheetTotal: 19; PageSetup: Record=PageOptions¦CenterHorizontal=True¦CenterVertical=True¦PrintScale=1.00¦XCorrection=1.00¦YCorrection=1.00¦PrintKind=0¦BorderSize=5000000¦LeftOffset=0¦BottomOffset=0¦Orientation=2¦PaperLength=1000¦PaperWidth=1000¦Scale=100¦PaperSource=15¦PrintQuality=600¦MediaType=1¦DitherType=10¦PaperKind=Letter¦PrintScaleMode=1
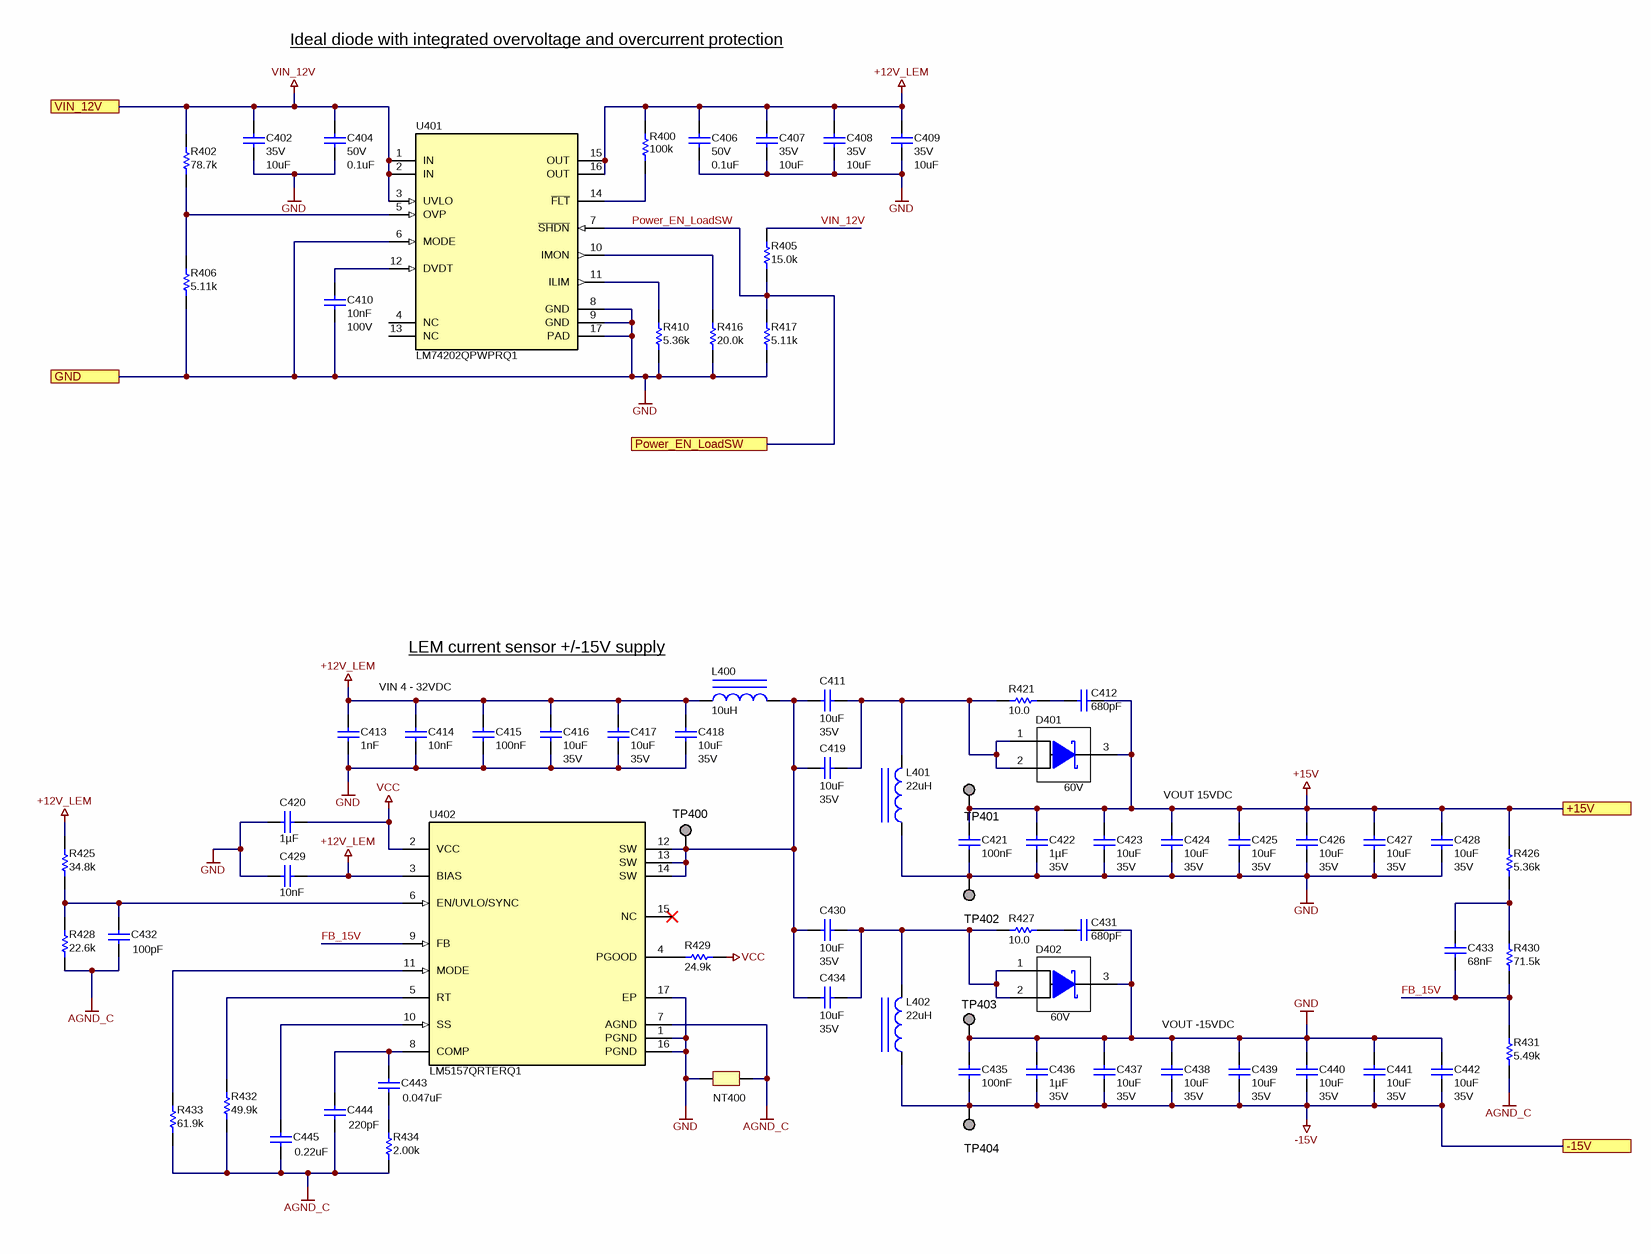
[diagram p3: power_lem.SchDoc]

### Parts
C402  VDC_V: 35V  ValueDisplayed: 10uF  [0603]  (hidden comment: GRM188R6YA106MA73D)
C404  VDC_V: 50V  ValueDisplayed: 0.1uF  [0603]  (hidden comment: CGA3E2X7R1H104K080AA)
C406  VDC_V: 50V  ValueDisplayed: 0.1uF  [0603]  (hidden comment: CGA3E2X7R1H104K080AA)
C407  VDC_V: 35V  ValueDisplayed: 10uF  [0603]  (hidden comment: GRM188R6YA106MA73D)
C408  VDC_V: 35V  ValueDisplayed: 10uF  [0603]  (hidden comment: GRM188R6YA106MA73D)
C409  VDC_V: 35V  ValueDisplayed: 10uF  [0603]  (hidden comment: GRM188R6YA106MA73D)
C410  Cap_F: 10nF  VDC_V: 100V  [0603]  (hidden comment: CGA3E2X7R2A103K080AA)
C411  ValueDisplayed: 10uF  VDC_V: 35V  [0603]  (hidden comment: GRM188R6YA106MA73D)
C412  ValueDisplayed: 680pF  [0603]  (hidden comment: C0603C681J5GACTU)
C413  Cap_F: 1nF  [0603]  (hidden comment: GRM1885C1H102JA01D)
C414  Cap_F: 10nF  [0603]  (hidden comment: CGA3E2X7R2A103K080AA)
C415  Cap_F: 100nF  [0603]  (hidden comment: CGA3E2X7R1H104K080AA)
C416  ValueDisplayed: 10uF  VDC_V: 35V  [0603]  (hidden comment: GRM188R6YA106MA73D)
C417  ValueDisplayed: 10uF  VDC_V: 35V  [0603]  (hidden comment: GRM188R6YA106MA73D)
C418  ValueDisplayed: 10uF  VDC_V: 35V  [0603]  (hidden comment: GRM188R6YA106MA73D)
C419  ValueDisplayed: 10uF  VDC_V: 35V  [0603]  (hidden comment: GRM188R6YA106MA73D)
C420  Cap_F: 1µF  [0603]  (hidden comment: CGA3E1X7R1V105K080AC)
C421  Cap_F: 100nF  [0603]  (hidden comment: CGA3E2X7R1H104K080AA)
C422  Cap_F: 1µF  VDC_V: 35V  [0603]  (hidden comment: CGA3E1X7R1V105K080AC)
C423  ValueDisplayed: 10uF  VDC_V: 35V  [0603]  (hidden comment: GRM188R6YA106MA73D)
C424  ValueDisplayed: 10uF  VDC_V: 35V  [0603]  (hidden comment: GRM188R6YA106MA73D)
C425  ValueDisplayed: 10uF  VDC_V: 35V  [0603]  (hidden comment: GRM188R6YA106MA73D)
C426  ValueDisplayed: 10uF  VDC_V: 35V  [0603]  (hidden comment: GRM188R6YA106MA73D)
C427  ValueDisplayed: 10uF  VDC_V: 35V  [0603]  (hidden comment: GRM188R6YA106MA73D)
C428  ValueDisplayed: 10uF  VDC_V: 35V  [0603]  (hidden comment: GRM188R6YA106MA73D)
C429  Cap_F: 10nF  [0603]  (hidden comment: CGA3E2X7R2A103K080AA)
C430  ValueDisplayed: 10uF  VDC_V: 35V  [0603]  (hidden comment: GRM188R6YA106MA73D)
C431  ValueDisplayed: 680pF  [0603]  (hidden comment: C0603C681J5GACTU)
C432  ValueDisplayed: 100pF  [0603]  (hidden comment: CGA3E2NP01H101J080AA)
C433  Cap_F: 68nF  [0603]  (hidden comment: CGA3E2X7R1H683K080AA)
C434  ValueDisplayed: 10uF  VDC_V: 35V  [0603]  (hidden comment: GRM188R6YA106MA73D)
C435  Cap_F: 100nF  [0603]  (hidden comment: CGA3E2X7R1H104K080AA)
C436  Cap_F: 1µF  VDC_V: 35V  [0603]  (hidden comment: CGA3E1X7R1V105K080AC)
C437  ValueDisplayed: 10uF  VDC_V: 35V  [0603]  (hidden comment: GRM188R6YA106MA73D)
C438  ValueDisplayed: 10uF  VDC_V: 35V  [0603]  (hidden comment: GRM188R6YA106MA73D)
C439  ValueDisplayed: 10uF  VDC_V: 35V  [0603]  (hidden comment: GRM188R6YA106MA73D)
C440  ValueDisplayed: 10uF  VDC_V: 35V  [0603]  (hidden comment: GRM188R6YA106MA73D)
C441  ValueDisplayed: 10uF  VDC_V: 35V  [0603]  (hidden comment: GRM188R6YA106MA73D)
C442  ValueDisplayed: 10uF  VDC_V: 35V  [0603]  (hidden comment: GRM188R6YA106MA73D)
C443  ValueDisplayed: 0.047uF  [0603]  (hidden comment: CGA3E2X7R1H473K080AA)
C444  ValueDisplayed: 220pF  [0603]  (hidden comment: GCM1885C2A221JA16D)
C445  ValueDisplayed: 0.22uF  [0603]  (hidden comment: GCM188R71E224KA55D)
D401  value 60V  [SOT1289]  (hidden comment: PMEG060V100EPDZ)
D402  value 60V  [SOT1289]  (hidden comment: PMEG060V100EPDZ)
L400  ValueDisplayed: 10uH  [MSS1278T]  (hidden comment: MSS1278T-103MLB)
L401  ValueDisplayed: 22uH  [MSS1278T]  (hidden comment: MSS1278T-223MLB)
L402  ValueDisplayed: 22uH  [MSS1278T]  (hidden comment: MSS1278T-223MLB)
NT400  Net-Tie  [Net-Tie_10mil]  (value not drawn)  (net tie, no BOM)
R400  ValueDisplayed: 100k  [0603]  (hidden comment: CRCW0603100KFKEA)
R402  ValueDisplayed: 78.7k  [0603]  (hidden comment: CRCW060378K7FKEA)
R405  ValueDisplayed: 15.0k  [0603]  (hidden comment: CRCW060315K0FKEA)
R406  ValueDisplayed: 5.11k  [0603]  (hidden comment: CRCW06035K11FKEA)
R410  ValueDisplayed: 5.36k  [0603]  (hidden comment: CRCW06035K36FKEA)
R416  ValueDisplayed: 20.0k  [0603]  (hidden comment: CRCW060320K0FKEA)
R417  ValueDisplayed: 5.11k  [0603]  (hidden comment: CRCW06035K11FKEA)
R421  ValueDisplayed: 10.0  [1210]  (hidden comment: CRCW121010R0FKEAHP)
R425  ValueDisplayed: 34.8k  [0603]  (hidden comment: CRCW060334K8FKEA)
R426  ValueDisplayed: 5.36k  [0603]  (hidden comment: CRCW06035K36FKEA)
R427  ValueDisplayed: 10.0  [1210]  (hidden comment: CRCW121010R0FKEAHP)
R428  ValueDisplayed: 22.6k  [0603]  (hidden comment: CRCW060322K6FKEA)
R429  ValueDisplayed: 24.9k  [0603]  (hidden comment: CRCW060324K9FKEA)
R430  ValueDisplayed: 71.5k  [0603]  (hidden comment: CRCW060371K5FKEA)
R431  ValueDisplayed: 5.49k  [0603]  (hidden comment: CRCW06035K49FKEA)
R432  ValueDisplayed: 49.9k  [0603]  (hidden comment: CRCW060349K9FKEA)
R433  ValueDisplayed: 61.9k  [0603]  (hidden comment: CRCW060361K9FKEA)
R434  ValueDisplayed: 2.00k  [0603]  (hidden comment: CRCW06032K00FKEA)
TP400  RCU-0C  [TE_RCU]  (value not drawn)
TP401  RCU-0C  [TE_RCU]  (value not drawn)
TP402  RCU-0C  [TE_RCU]  (value not drawn)
TP403  RCU-0C  [TE_RCU]  (value not drawn)
TP404  RCU-0C  [TE_RCU]  (value not drawn)
U401  LM74202QPWPRQ1  [PWP0016J_N]
U402  LM5157QRTERQ1  [RTE0016K]

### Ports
+15V, -15V, GND, Power_EN_LoadSW, VIN_12V

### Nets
+12V_LEM: C406.1 C407.1 C408.1 C409.1 C413.1 C414.1 C415.1 C416.1 C417.1 C418.1 C429.1 L400.1 R400.2 R425.2 U401.15(OUT) U401.16(OUT) U402.3(BIAS)
+15V: C412.1 C421.1 C422.1 C423.2 C424.2 C425.2 C426.2 C427.2 C428.2 D401.3(K) R426.2 TP401.1 ; port +15V
-15V: C435.2 C436.2 C437.1 C438.1 C439.1 C440.1 C441.1 C442.1 L402.2 TP404.1 ; port -15V
AGND_C: C432.2 C444.2 C445.2 NT400.2 R428.1 R431.1 R432.1 R433.1 R434.1 U402.7(AGND)
GND: C402.2 C404.2 C406.2 C407.2 C408.2 C409.2 C410.2 C413.2 C414.2 C415.2 C416.2 C417.2 C418.2 C420.1 C421.2 C422.2 C423.1 C424.1 C425.1 C426.1 C427.1 C428.1 C429.2 C431.1 C435.1 C436.1 C437.2 C438.2 C439.2 C440.2 C441.2 C442.2 D402.3(K) L401.1 NT400.1 R406.1 R410.1 R416.1 R417.1 TP402.1 TP403.1 U401.6(MODE) U401.8(GND) U401.9(GND) U401.17(PAD) U402.1(PGND) U402.16(PGND) U402.17(EP) ; port GND
VCC: C420.2 R429.2 U402.2(VCC)
VIN_12V: C402.1 C404.1 R402.2 R405.2 U401.1(IN) U401.2(IN) U401.3(UVLO) ; port VIN_12V
FB_15V: C433.2 R430.1 R431.2 U402.9(FB)  [project net FB_15V_4]
Power_EN_LoadSW: R405.1 R417.2 U401.7(~{SHDN}) ; port Power_EN_LoadSW
NetC410_1: C410.1 U401.12(DVDT)
NetC411_1: C411.1 C419.1 C430.1 C434.1 L400.2 TP400.1 U402.12(SW) U402.13(SW) U402.14(SW)
NetC411_2: C411.2 C419.2 D401.1(A) D401.2(A) L401.2 R421.1
NetC412_2: C412.2 R421.2
NetC430_2: C430.2 C434.2 D402.1(A) D402.2(A) L402.1 R427.1
NetC431_2: C431.2 R427.2
NetC432_1: C432.1 R425.1 R428.2 U402.6(EN/UVLO/SYNC)
NetC433_1: C433.1 R426.1 R430.2
NetC443_1: C443.1 C444.1 U402.8(COMP)
NetC443_2: C443.2 R434.2
NetC445_1: C445.1 U402.10(SS)
NetR400_1: R400.1 U401.14(~{FLT})
NetR402_1: R402.1 R406.2 U401.5(OVP)
NetR410_2: R410.2 U401.11(ILIM)
NetR416_2: R416.2 U401.10(IMON)
NetR429_1: R429.1 U402.4(PGOOD)
NetR432_2: R432.2 U402.5(RT)
NetR433_2: R433.2 U402.11(MODE)

Not connected (* = marked no-connect by the designer): U401 4(NC) 13(NC); U402 15(NC)*

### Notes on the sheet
- Ideal diode with integrated overvoltage and overcurrent protection
- LEM current sensor +/-15V supply
- VIN 4 - 32VDC
- VOUT 15VDC
- VOUT -15VDC

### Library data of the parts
C402 C407-C409 = CMP-0007355-6: as C300 on sheet power_ls
C404 C406 = CMP-0007078-4: as C301 on sheet power_ls
C410 = CMP-0007082-4: as C310 on sheet power_ls
C411 C416-C419 C423-C428 C430 C434 C437-C442 = CMP-0007355-6: as C320-C322 on sheet power_ls
C412 C431 = CMP-0006959-4: as C316 on sheet power_ls
C413 = CMP-0007173-4: as C317 on sheet power_ls
C414 = CMP-0007082-4: as C318 on sheet power_ls
C415 C421 C435 = CMP-0007078-4: as C319 on sheet power_ls
C420 = CMP-0007067-4: as C311 on sheet power_ls
C422 C436 = CMP-0007067-4: CAP, CERM, 1 uF, 35 V, +/- 10%, X7R, AEC-Q200 Grade 1, 0603; Manufacturer: TDK; TaMin_C: -55°C; Polarized: N; SizeAreaWB_mm2: 4.68; Value1: 0.005522 ohm; U/M: EA; Value: 1uF; TaMax_C: 125°C; SizeZ_mm: 1; SizeX_mm: 1.6; SizeY_mm: 0.8; SizeArea_mm2: 1.28; AEC Qualified: Y; AEC Category: Q200; ESR_ohm: 5.522m; IRMS_A: 2.2162A
C429 = CMP-0007082-4: as C328 on sheet power_ls
C432 = CMP-0007075-4: as C337 on sheet power_ls
C433 = CMP-0007080-5: as C336 on sheet power_ls
C443 = CMP-0007079-4: as C338 on sheet power_ls
C444 = CMP-0860912-1: as C343 on sheet power_ls
C445 = CMP-0007140-4: as C312 on sheet power_ls
D401 D402 = CMP-0028984-3: as D300 on sheet power_ls
L400 = CMP-0060638-1: Inductor, Shielded Drum Core, Ferrite, 10 uH, 5.7 A, 0.02 ohm, SMD; Manufacturer: Coilcraft; Isat: 12.48A @ 30% inductance drop; Irms: 5.7A @ 40C rise; Green_Lifecycle: Not Set; SizeAreaWB_mm2: 196; DCR_ohm: 20m; Green_REACh: Incomplete; Value: 10uH; Imax_A: 5.7A; SizeZ_mm: 8; SizeX_mm: 12; SizeArea_mm2: 144; Ind_H: 10µH; AEC Category: Q200
L401 L402 = CMP-0061523-2: Inductor, Shielded Drum Core, Ferrite, 22 uH, 4 A, 0.04 ohm, SMD; Manufacturer: Coilcraft; Isat: 8.34A @ 30% inductance drop; Irms: 4A @ 40C rise; Green_Lifecycle: Not Set; SizeAreaWB_mm2: 196; DCR_ohm: 40m; Green_REACh: Incomplete; Value: 22uH; Imax_A: 4A; SizeZ_mm: 8; SizeX_mm: 12; SizeArea_mm2: 144; Ind_H: 22µH; AEC Category: Q200
NT400 = CMP-0078142-6: Single point connection between nets.
R400 = CMP-0021990-4: as R300 on sheet power_ls
R402 = CMP-0022597-4: as R301 on sheet power_ls
R405 = CMP-0022066-4: as R302 on sheet power_ls
R406 = CMP-0022509-4: as R303 on sheet power_ls
R410 R426 = CMP-0022511-4: as R304 on sheet power_ls
R416 = CMP-0022204-4: as R305 on sheet power_ls
R417 = CMP-0022509-4: as R306 on sheet power_ls
R421 R427 = CMP-0015019-3: as R309 on sheet power_ls
R425 = CMP-0022347-4: as R310 on sheet power_ls
R428 = CMP-0022221-4: as R314 on sheet power_ls
R429 = CMP-0022237-4: as R312 on sheet power_ls
R430 = CMP-0022581-4: RES, 71.5 k, 1%, 0.1 W, AEC-Q200 Grade 0, 0603; Manufacturer: Vishay-Dale; Power_W: 100mW; TempCo: 100 ppm/C; Value_Code: 71k5; Value: 71.5k; EIA_Code: E96; SizeX_mm: 1.6; SizeY_mm: 0.8; SizeZ_mm: 1; Value2: 0.1W; SizeArea_mm2: 1.28; AEC Qualified: Y; VDC_V: 75V; AEC Category: Q200; AEC Grade: 0
R431 = CMP-0022512-4: as R315 on sheet power_ls
R432 = CMP-0022447-4: as R316 on sheet power_ls
R433 = CMP-0022536-4: as R317 on sheet power_ls
R434 = CMP-0022268-4: as R318 on sheet power_ls
TP400-TP404 = CMP-0067620-1: as TP301 on sheet power_ls
U401 = CMP-0086311-1: as U301 on sheet power_ls
U402 = CMP-0861102-1: 2.2MHz Wide VIN Boost/Sepic/Flyback Converter with Dual Random Spread Spectrum, RTE0016K (WQFN-16); Alternate Manufacturer: Texas Instruments; SizeX_mm: 3; SizeZ_mm: 0.8; SizeArea_mm2: 9; SizeAreaWB_mm2: 16; AEC Category: Q200; CompType: IC; AEC Qualified: N

## Sheet can_lin_interface.SchDoc: Communication Interfaces
size 431 x 279 mm; Date: Not shown in title block; ApprovedBy: Not shown in title block; CheckedBy: Not shown in title block; Author: Not shown in title block; CompanyName: Not shown in title block; DrawnBy: Panacek; Engineer: Not shown in title block; Organization: Not shown in title block; Address1: Not shown in title block; Address2: Not shown in title block; Address3: Not shown in title block; Address4: Not shown in title block; DocumentNumber: 6; Revision: Use project parameter SCH_Rev; SheetNumber: 6; SheetTotal: 19; PageSetup: Record=PageOptions¦CenterHorizontal=True¦CenterVertical=True¦PrintScale=1.00¦XCorrection=1.00¦YCorrection=1.00¦PrintKind=0¦BorderSize=5000000¦LeftOffset=0¦BottomOffset=0¦Orientation=2¦PaperLength=1000¦PaperWidth=1000¦Scale=100¦PaperSource=15¦PrintQuality=600¦MediaType=1¦DitherType=10¦PaperKind=Letter¦PrintScaleMode=1
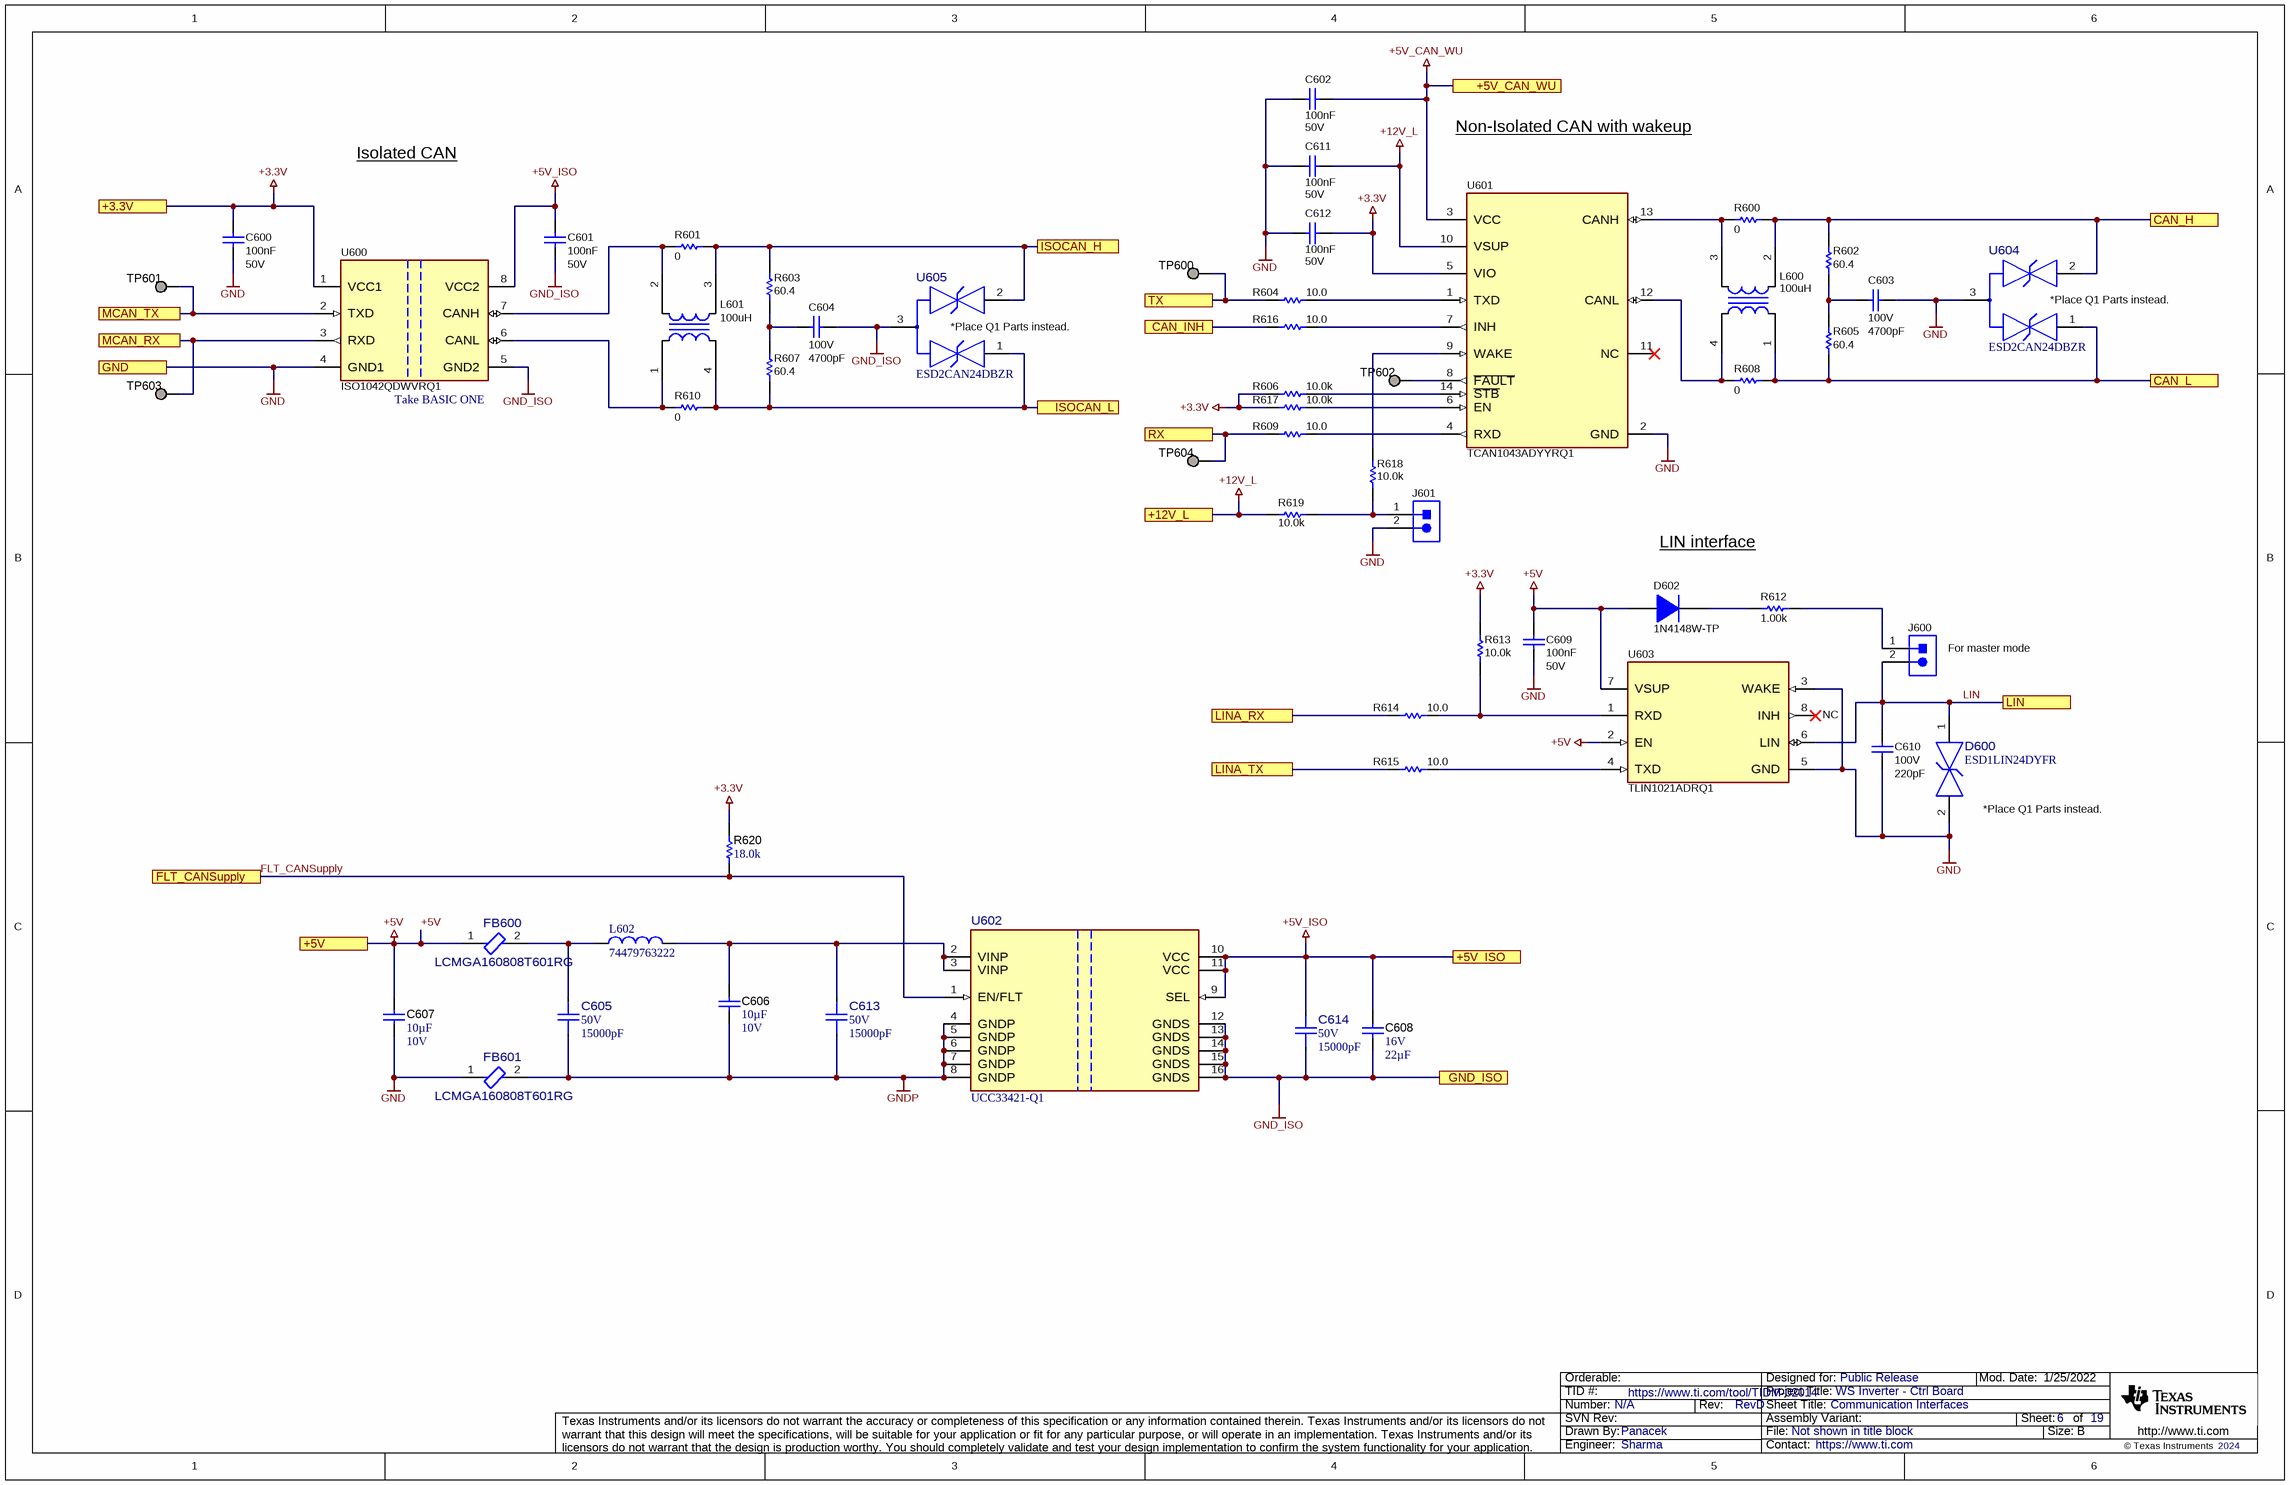
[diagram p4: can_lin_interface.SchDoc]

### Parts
C600  Cap_F: 100nF  VDC_V: 50V  [0603]  (hidden comment: CGA3E2X7R1H104K080AA)
C601  Cap_F: 100nF  VDC_V: 50V  [0603]  (hidden comment: CGA3E2X7R1H104K080AA)
C602  Cap_F: 100nF  VDC_V: 50V  [0603]  (hidden comment: CGA3E2X7R1H104K080AA)
C603  VDC_V: 100V  ValueDisplayed: 4700pF  [0603]  (hidden comment: CGA3E2X7R2A472K080AA)
C604  VDC_V: 100V  ValueDisplayed: 4700pF  [0603]  (hidden comment: CGA3E2X7R2A472K080AA)
C605  VDC_V: 50V  ValueDisplayed: 15000pF  [FP-GCM155R71H153KA55D_0402-MFG]  (hidden comment: GCM155R71H153KA55D)
C606  Cap_F: 10µF  VDC_V: 10V  [0805_HV]  (hidden comment: GCJ21BR71A106KE01L)
C607  Cap_F: 10µF  VDC_V: 10V  [0805_HV]  (hidden comment: GCJ21BR71A106KE01L)
C608  VDC_V: 16V  ValueDisplayed: 22µF  [0603]  (hidden comment: CL10A226MO7JZNC)
C609  Cap_F: 100nF  VDC_V: 50V  [0603]  (hidden comment: CGA3E2X7R1H104K080AA)
C610  VDC_V: 100V  ValueDisplayed: 220pF  [0603]  (hidden comment: GCM1885C2A221JA16D)
C611  Cap_F: 100nF  VDC_V: 50V  [0603]  (hidden comment: CGA3E2X7R1H104K080AA)
C612  Cap_F: 100nF  VDC_V: 50V  [0603]  (hidden comment: CGA3E2X7R1H104K080AA)
C613  VDC_V: 50V  ValueDisplayed: 15000pF  [FP-GCM155R71H153KA55D_0402-MFG]  (hidden comment: GCM155R71H153KA55D)
C614  VDC_V: 50V  ValueDisplayed: 15000pF  [FP-GCM155R71H153KA55D_0402-MFG]  (hidden comment: GCM155R71H153KA55D)
D600  ESD1LIN24DYFR  [DYF0002A-MFG]
D602  1N4148W-TP  [SOD-123]
FB600  LCMGA160808T601RG  [FP-LCMGA160808T601RG_0603-MFG]
FB601  LCMGA160808T601RG  [FP-LCMGA160808T601RG_0603-MFG]
J600  TSW-102-07-G-S  [TSW-102-07-G-S]  (value not drawn)
J601  TSW-102-07-G-S  [TSW-102-07-G-S]  (value not drawn)
L600  ValueDisplayed: 100uH  [ACT45B]  (hidden comment: ACT45B-101-2P-TL003)
L601  ValueDisplayed: 100uH  [ACT45B]  (hidden comment: ACT45B-101-2P-TL003)
L602  74479763222  [WE-PMI_0603_L1.6W0.8H0.8]
R600  ValueDisplayed: 0  [0603]  (hidden comment: CRCW06030000Z0EA)
R601  ValueDisplayed: 0  [0603]  (hidden comment: CRCW06030000Z0EA)
R602  ValueDisplayed: 60.4  [0603]  (hidden comment: CRCW060360R4FKEA)
R603  ValueDisplayed: 60.4  [0603]  (hidden comment: CRCW060360R4FKEA)
R604  ValueDisplayed: 10.0  [0603]  (hidden comment: CRCW060310R0FKEA)
R605  ValueDisplayed: 60.4  [0603]  (hidden comment: CRCW060360R4FKEA)
R606  ValueDisplayed: 10.0k  [0603]  (hidden comment: CRCW060310K0FKEA)
R607  ValueDisplayed: 60.4  [0603]  (hidden comment: CRCW060360R4FKEA)
R608  ValueDisplayed: 0  [0603]  (hidden comment: CRCW06030000Z0EA)
R609  ValueDisplayed: 10.0  [0603]  (hidden comment: CRCW060310R0FKEA)
R610  ValueDisplayed: 0  [0603]  (hidden comment: CRCW06030000Z0EA)
R612  ValueDisplayed: 1.00k  [0603]  (hidden comment: CRCW06031K00FKEA)
R613  ValueDisplayed: 10.0k  [0603]  (hidden comment: CRCW060310K0FKEA)
R614  ValueDisplayed: 10.0  [0603]  (hidden comment: CRCW060310R0FKEA)
R615  ValueDisplayed: 10.0  [0603]  (hidden comment: CRCW060310R0FKEA)
R616  ValueDisplayed: 10.0  [0603]  (hidden comment: CRCW060310R0FKEA)
R617  ValueDisplayed: 10.0k  [0603]  (hidden comment: CRCW060310K0FKEA)
R618  ValueDisplayed: 10.0k  [0603]  (hidden comment: CRCW060310K0FKEA)
R619  ValueDisplayed: 10.0k  [0603]  (hidden comment: CRCW060310K0FKEA)
R620  ValueDisplayed: 18.0k  [0603]  (hidden comment: RC0603FR-0718KL)
TP600  RCU-0C  [TE_RCU]  (value not drawn)
TP601  RCU-0C  [TE_RCU]  (value not drawn)
TP602  RCU-0C  [TE_RCU]  (value not drawn)
TP603  RCU-0C  [TE_RCU]  (value not drawn)
TP604  RCU-0C  [TE_RCU]  (value not drawn)
U600  ISO1042QDWVRQ1  [DWV0008A-MFG]
U601  TCAN1043ADYYRQ1  [DYY0014A-MFG]
U602  UCC33421-Q1  [DWX0016A-MFG]
U603  TLIN1021ADRQ1  [D0008A-MFG]
U604  ESD2CAN24DBZR  [DBZ0003A-MFG]
U605  ESD2CAN24DBZR  [DBZ0003A-MFG]

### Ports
+3.3V, +5V, +5V_CAN_WU, +5V_ISO, +12V_L, CAN_H, CAN_INH, CAN_L, FLT_CANSupply, GND, GND_ISO, ISOCAN_H, ISOCAN_L, LIN, LINA_RX, LINA_TX, MCAN_RX, MCAN_TX, RX, TX

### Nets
+3.3V: C600.1 C612.2 R606.1 R613.2 R617.1 R620.2 U600.1(VCC1) U601.5(VIO) ; port +3.3V
+5V: C607.1 C609.1 D602.2(A) FB600.1 U603.2(EN) U603.7(VSUP) ; port +5V
+5V_CAN_WU: C602.2 U601.3(VCC) ; port +5V_CAN_WU
+5V_ISO: C601.1 C608.1 C614.2 U600.8(VCC2) U602.9(SEL) U602.10(VCC) U602.11(VCC) ; port +5V_ISO
+12V_L: C611.2 R619.2 U601.10(VSUP) ; port +12V_L
GND: C600.2 C602.1 C603.1 C607.2 C609.2 C610.2 C611.1 C612.1 D600.2(GND) FB601.1 J601.2 U600.4(GND1) U601.2(GND) U603.3(WAKE) U603.5(GND) U604.3(GND) ; port GND
GND_ISO: C601.2 C604.1 C608.2 C614.1 U600.5(GND2) U602.12(GNDS) U602.13(GNDS) U602.14(GNDS) U602.15(GNDS) U602.16(GNDS) U605.3(GND) ; port GND_ISO
GNDP: C605.1 C606.2 C613.1 FB601.2 U602.4(GNDP) U602.5(GNDP) U602.6(GNDP) U602.7(GNDP) U602.8(GNDP)
CAN_H: L600.2 R600.2 R602.2 U604.2(2_IO) ; port CAN_H
CAN_INH: R616.1 ; port CAN_INH
CAN_L: L600.1 R605.1 R608.2 U604.1(1_IO) ; port CAN_L
FLT_CANSupply: R620.1 U602.1(EN/FLT) ; port FLT_CANSupply
ISOCAN_H: L601.3 R601.2 R603.2 U605.2(2_IO) ; port ISOCAN_H
ISOCAN_L: L601.4 R607.1 R610.2 U605.1(1_IO) ; port ISOCAN_L
LIN: C610.1 D600.1(IO) J600.2 U603.6(LIN) ; port LIN
LINA_RX: R614.1 ; port LINA_RX
LINA_TX: R615.1 ; port LINA_TX
MCAN_RX: TP603.1 U600.3(RXD) ; port MCAN_RX
MCAN_TX: TP601.1 U600.2(TXD) ; port MCAN_TX
RX: R609.1 TP604.1 ; port RX
TX: R604.1 TP600.1 ; port TX
NetC603_2: C603.2 R602.1 R605.2
NetC604_2: C604.2 R603.1 R607.2
NetC605_2: C605.2 FB600.2 L602.1
NetC606_1: C606.1 C613.2 L602.2 U602.2(VINP) U602.3(VINP)
NetD602_1: D602.1(K) R612.2
NetJ600_1: J600.1 R612.1
NetJ601_1: J601.1 R618.1 R619.1
NetL600_3: L600.3 R600.1 U601.13(CANH)
NetL600_4: L600.4 R608.1 U601.12(CANL)
NetL601_1: L601.1 R610.1 U600.6(CANL)
NetL601_2: L601.2 R601.1 U600.7(CANH)
NetR604_2: R604.2 U601.1(TXD)
NetR606_2: R606.2 U601.14(~{STB})
NetR609_2: R609.2 U601.4(RXD)
NetR613_1: R613.1 R614.2 U603.1(RXD)
NetR615_2: R615.2 U603.4(TXD)
NetR616_2: R616.2 U601.7(INH)
NetR617_2: R617.2 U601.6(EN)
NetR618_2: R618.2 U601.9(WAKE)
NetTP602_1: TP602.1 U601.8(~{FAULT})

Not connected (* = marked no-connect by the designer): U601 11(NC)*; U603 8(INH)*

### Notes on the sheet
- Isolated CAN
- Non-Isolated CAN with wakeup
- (near U604) *Place Q1 Parts instead.
- (near U605) *Place Q1 Parts instead.
- (near U600) Take BASIC ONE
- LIN interface
- (near J600) For master mode
- NC
- (near D600) *Place Q1 Parts instead.

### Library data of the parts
C600-C602 C609 C611 C612 = CMP-0007078-4: as C325 on sheet power_ls
C603 C604 = CMP-0007088-4: CAP, CERM, 4700 pF, 100 V, +/- 10%, X7R, AEC-Q200 Grade 1, 0603; Manufacturer: TDK; TaMin_C: -55°C; ESR_ohm: 0.4699; Polarized: N; SizeAreaWB_mm2: 4.68; Value1: 0.469862 ohm; U/M: EA; Value: 4700pF; TaMax_C: 125°C; SizeZ_mm: 1; SizeX_mm: 1.6; SizeY_mm: 0.8; SizeArea_mm2: 1.28; AEC Qualified: Y; Cap_F: 4.7nF; IRMS_A: 323.35mA; AEC Category: Q200
C605 C613 C614 = CMP-0090630-1: 0.015µF ±10% 50V Ceramic Capacitor X7R 0402 (1005 Metric); Manufacturer: Murata; SizeZ_mm: 0.55mm; AEC Qualified: Yes; AEC Grade: Grade 1; Value: 15nF; TempCo: 15%
C606 C607 = CMP-0079153-1: CAP, CERM, 10 µF, 10 V,+/- 10%, X7R, AEC-Q200 Grade 1, 0805; Manufacturer: MuRata; SizeAreaWB_mm2: 6.75; SizeArea_mm2: 2.5; AEC Qualified: Y; AEC Category: Q200; Value: 10uF; TaMax_C: 125°C; SizeZ_mm: 1.45; AEC Grade: 1; Polarized: N; TaMin_C: -55°C; SizeY_mm: 1.25; U/M: EA; SizeX_mm: 2; Cap_Case: 0805
C608 = CMP-0081159-1: CAP, CERM, 22 µF, 16 V,+/- 20%, X5R, 0603; Manufacturer: Samsung; SizeAreaWB_mm2: 4.68; SizeArea_mm2: 1.28; AEC Qualified: N; AEC Category: Q200; Value: 22uF; TaMax_C: 85°C; SizeZ_mm: 1; TaMin_C: -55°C; SizeY_mm: 0.8; U/M: EA; SizeX_mm: 1.6
C610 = CMP-0860912-1: CAP, CERM, 220 pF, 100 V,+/- 5%, C0G/NP0, AEC-Q200 Grade 1, 0603; Manufacturer: MuRata; TaMin_C: -55°C; Polarized: N; SizeAreaWB_mm2: 4.68; U/M: EA; Value: 220pF; TaMax_C: 125°C; SizeZ_mm: 1; SizeX_mm: 1.6; SizeY_mm: 0.8; SizeArea_mm2: 1.28; AEC Qualified: Y; AEC Category: Q200
D600 = CMP-0098376-1: 24-V, 1-Channel ESD Protection Diode; Manufacturer: Texas Instruments; AEC Qualified: No; SizeZ_mm: 1mm; VRWM: 24V; Ipp: 16A; Ppk: 159.1W; Breakdown Voltage: 25.5V; Cap_F: 2.3pF; Clamping Voltage: 40V; Direction: Bidirectional; Number Of Channels: 1; Standoff Height: 0mm; TaMax_C: +150°C; TaMin_C: -55°C
D602 = CMP-0076974-2: Diode, Switching, 100 V, 0.15 A, SOD-123; Manufacturer: Micro Commercial Components; Io_A: 150mA; SizeX_mm: 3.85; SizeY_mm: 1.7; Green_REACh: Incomplete; AEC Category: Q101; TJmax_C: 150°C; Value1: 0.15A; Vf_V: 1.25V; Value: 100V; SizeZ_mm: 1.35; SizeArea_mm2: 6.545; SizeAreaWB_mm2: 13.095; Green_Lifecycle: Not Set
FB600 FB601 = CMP-0124053-1: Ferrite Bead 600Ohm 0.9A 0.17Ohm Wirewound 2-Pin 0603 Paper T/R; Manufacturer: Taiyo Yuden; DCR_ohm: 0.17; Imax_A: 900mA; SizeZ_mm: 0.9mm; AEC Grade: Grade 1; AEC Qualified: Yes; Impedance At Frequency: 600Ω @ 100MHz; Tolerance_%: 25%
J600 J601 = CMP-0075405-3: Header, 100mil, 2x1, Gold, TH; Manufacturer: Samtec; Current_A: 6.3A; Green_Lifecycle: Active; Pitch_mm: 2.54; Cert_CSA: Y; Cert_VDE: N; Green_REACh: Passed; Row_Count: 1; Gender: Male; Voltage_V: 550V
L600 L601 = CMP-0062430-2: Inductor, Ferrite, 100 uH, 0.15 A, 2 ohm, SMD; Manufacturer: TDK; Isat: 0.15A @ % inductance drop; Green_Lifecycle: Active; SizeAreaWB_mm2: 23.1; DCR_ohm: 2; Green_REACh: Passed; Value1: 2 ohm; Value: 100uH; Imax_A: 150mA; SizeZ_mm: 3; SizeX_mm: 4.5; SizeY_mm: 3.2; Value2: 0.15A; SizeArea_mm2: 14.4; Ind_H: 100µH; AEC Category: Q200
L602 = CMP-1392-00025-2: NexarPartId: 38797936; Manufacturer: Wurth Elektronik; DC Resistance (DCR): 300mΩ; Inductance: 2.2µH; Current Rating: 550mA
R600 R601 R608 R610 = CMP-0025697-4: RES, 0, 5%, 0.1 W, AEC-Q200 Grade 0, 0603; Manufacturer: Vishay-Dale; Power_W: 100mW; TempCo: 200 ppm/C; Value_Code: 0000; Value: 0; SizeX_mm: 1.6; SizeY_mm: 0.8; SizeZ_mm: 1; Value2: 0.1W; SizeArea_mm2: 1.28; AEC Qualified: Y; AEC Category: Q200; EIA_Code: E24; VDC_V: 75V
R602 R603 R605 R607 = CMP-0022533-4: RES, 60.4, 1%, 0.1 W, AEC-Q200 Grade 0, 0603; Manufacturer: Vishay-Dale; Value: 60.4; Value_Code: 60R4; Power_W: 100mW; Value2: 0.1W; VDC_V: 75V; TempCo: 100 ppm/C; SizeArea_mm2: 1.28; SizeX_mm: 1.6; SizeY_mm: 0.8; SizeZ_mm: 1; EIA_Code: E96; AEC Category: Q200; AEC Qualified: Y; AEC Grade: 0
R604 R609 R614-R616 = CMP-0022003-4: RES, 10.0, 1%, 0.1 W, AEC-Q200 Grade 0, 0603; Manufacturer: Vishay-Dale; Value: 10.0; Res_ohm: 10; Value_Code: 10R0; Power_W: 100mW; Value2: 0.1W; VDC_V: 75V; TempCo: 100 ppm/C; SizeArea_mm2: 1.28; SizeX_mm: 1.6; SizeY_mm: 0.8; SizeZ_mm: 1; EIA_Code: E96; AEC Category: Q200; AEC Qualified: Y; AEC Grade: 0
R606 R617-R619 = CMP-0021998-4: RES, 10.0 k, 1%, 0.1 W, AEC-Q200 Grade 0, 0603; Manufacturer: Vishay-Dale; Power_W: 100mW; TempCo: 100 ppm/C; Value_Code: 10k0; Value: 10.0k; Res_ohm: 10k; SizeX_mm: 1.6; SizeY_mm: 0.8; SizeZ_mm: 1; Value2: 0.1W; SizeArea_mm2: 1.28; AEC Qualified: Y; AEC Grade: 0; AEC Category: Q200; EIA_Code: E96; VDC_V: 75V
R612 = CMP-0022109-5: RES, 1.00 k, 1%, 0.1 W, AEC-Q200 Grade 0, 0603; Manufacturer: Vishay-Dale; Power_W: 100mW; TempCo: 100 ppm/C; Value_Code: 1k00; Value: 1.00k; EIA_Code: E96; Res_ohm: 1k; SizeX_mm: 1.6; SizeY_mm: 0.8; SizeZ_mm: 1; Value2: 0.1W; SizeArea_mm2: 1.28; AEC Qualified: Y; AEC Category: Q200; AEC Grade: 0; VDC_V: 75V
R613 = CMP-0021998-4: RES, 10.0 k, 1%, 0.1 W, AEC-Q200 Grade 0, 0603; Manufacturer: Vishay-Dale; Value: 10.0k; Res_ohm: 10k; Value_Code: 10k0; Power_W: 100mW; Value2: 0.1W; VDC_V: 75V; TempCo: 100 ppm/C; EIA_Code: E96; AEC Category: Q200; AEC Qualified: Y; AEC Grade: 0; SizeArea_mm2: 1.28; SizeX_mm: 1.6; SizeY_mm: 0.8; SizeZ_mm: 1
R620 = CMP-0022852-5: RES, 18.0 k, 1%, 0.1 W, 0603; Manufacturer: Yageo; Power_W: 100mW; TempCo: 100 ppm/C; Value_Code: 18k0; Value: 18.0k; Res_ohm: 18k; SizeX_mm: 1.6; SizeY_mm: 0.8; SizeZ_mm: 1; Value2: 0.1W; SizeArea_mm2: 1.28; AEC Qualified: N; VDC_V: 75V; AEC Category: Q200; SizeAreaWB_mm2: 4.68
TP600-TP604 = CMP-0067620-1: as TP301 on sheet power_ls
U600 = CMP-0096963-1: Automotive Isolated CAN Transceiver With 70-V Bus Fault Protection and Flexible Data Rate; Manufacturer: Texas Instruments; SizeZ_mm: 2.8mm; AEC Qualified: Yes; Standoff Height: 0.36mm; AEC Grade: Grade 1; TaMax_C: +125°C; Max Supply Voltage: 5.5V; TJmax_C: +150°C; Min Supply Voltage: 1.71V; TaMin_C: -40°C
U601 = CMP-0089855-1: Low-Power Fault Protected CAN FD Transceiver with INH and WAKE; Manufacturer: Texas Instruments; Max Supply Voltage: 28V; Standoff Height: 0mm; Min Supply Voltage: 1.7V; AEC Grade: Grade 1; SizeZ_mm: 1.1mm; TJmax_C: +165°C; AEC Qualified: Yes
U602 = CMP-0120108-2: 1.5W, High-Density, >5 kVRMS Isolated DC-DC Converter; Manufacturer: Texas Instruments; SizeZ_mm: 2.6mm; AEC Qualified: No; Max Supply Voltage: 5.5V; Min Supply Voltage: 4.5V; Number Of Outputs: 1; Output Type: AdjustableProgrammable; Output Voltage: 5/5.5V; Standoff Height: 0.14mm; AEC Category: Q200; CompType: IC
U603 = CMP-0091357-1: Fault-Protected LIN Transceiver with Inhibit and Wake; Manufacturer: Texas Instruments; TJmax_C: +150°C; SizeZ_mm: 1.75mm; Max Supply Voltage: 36V; AEC Grade: Grade 1; AEC Qualified: Yes; Standoff Height: 0.11mm; Nominal Supply Current: 300-1200uA; Min Supply Voltage: 4.5V
U604 U605 = CMP-0093261-1: 24-V, 2-Channel ESD Protection Diode for In-Vehicle Networks; Manufacturer: Texas Instruments; Cap_F: 3pF; Breakdown Voltage: 25.5V; Clamping Voltage: 32V; TaMax_C: +150°C; Direction: Bidirectional; TaMin_C: -55°C; Ipp: 3.5A; VRWM: 24V; Standoff Height: 0.01mm; SizeZ_mm: 1.12mm; Ppk: 147W; AEC Qualified: No; Number Of Channels: 2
